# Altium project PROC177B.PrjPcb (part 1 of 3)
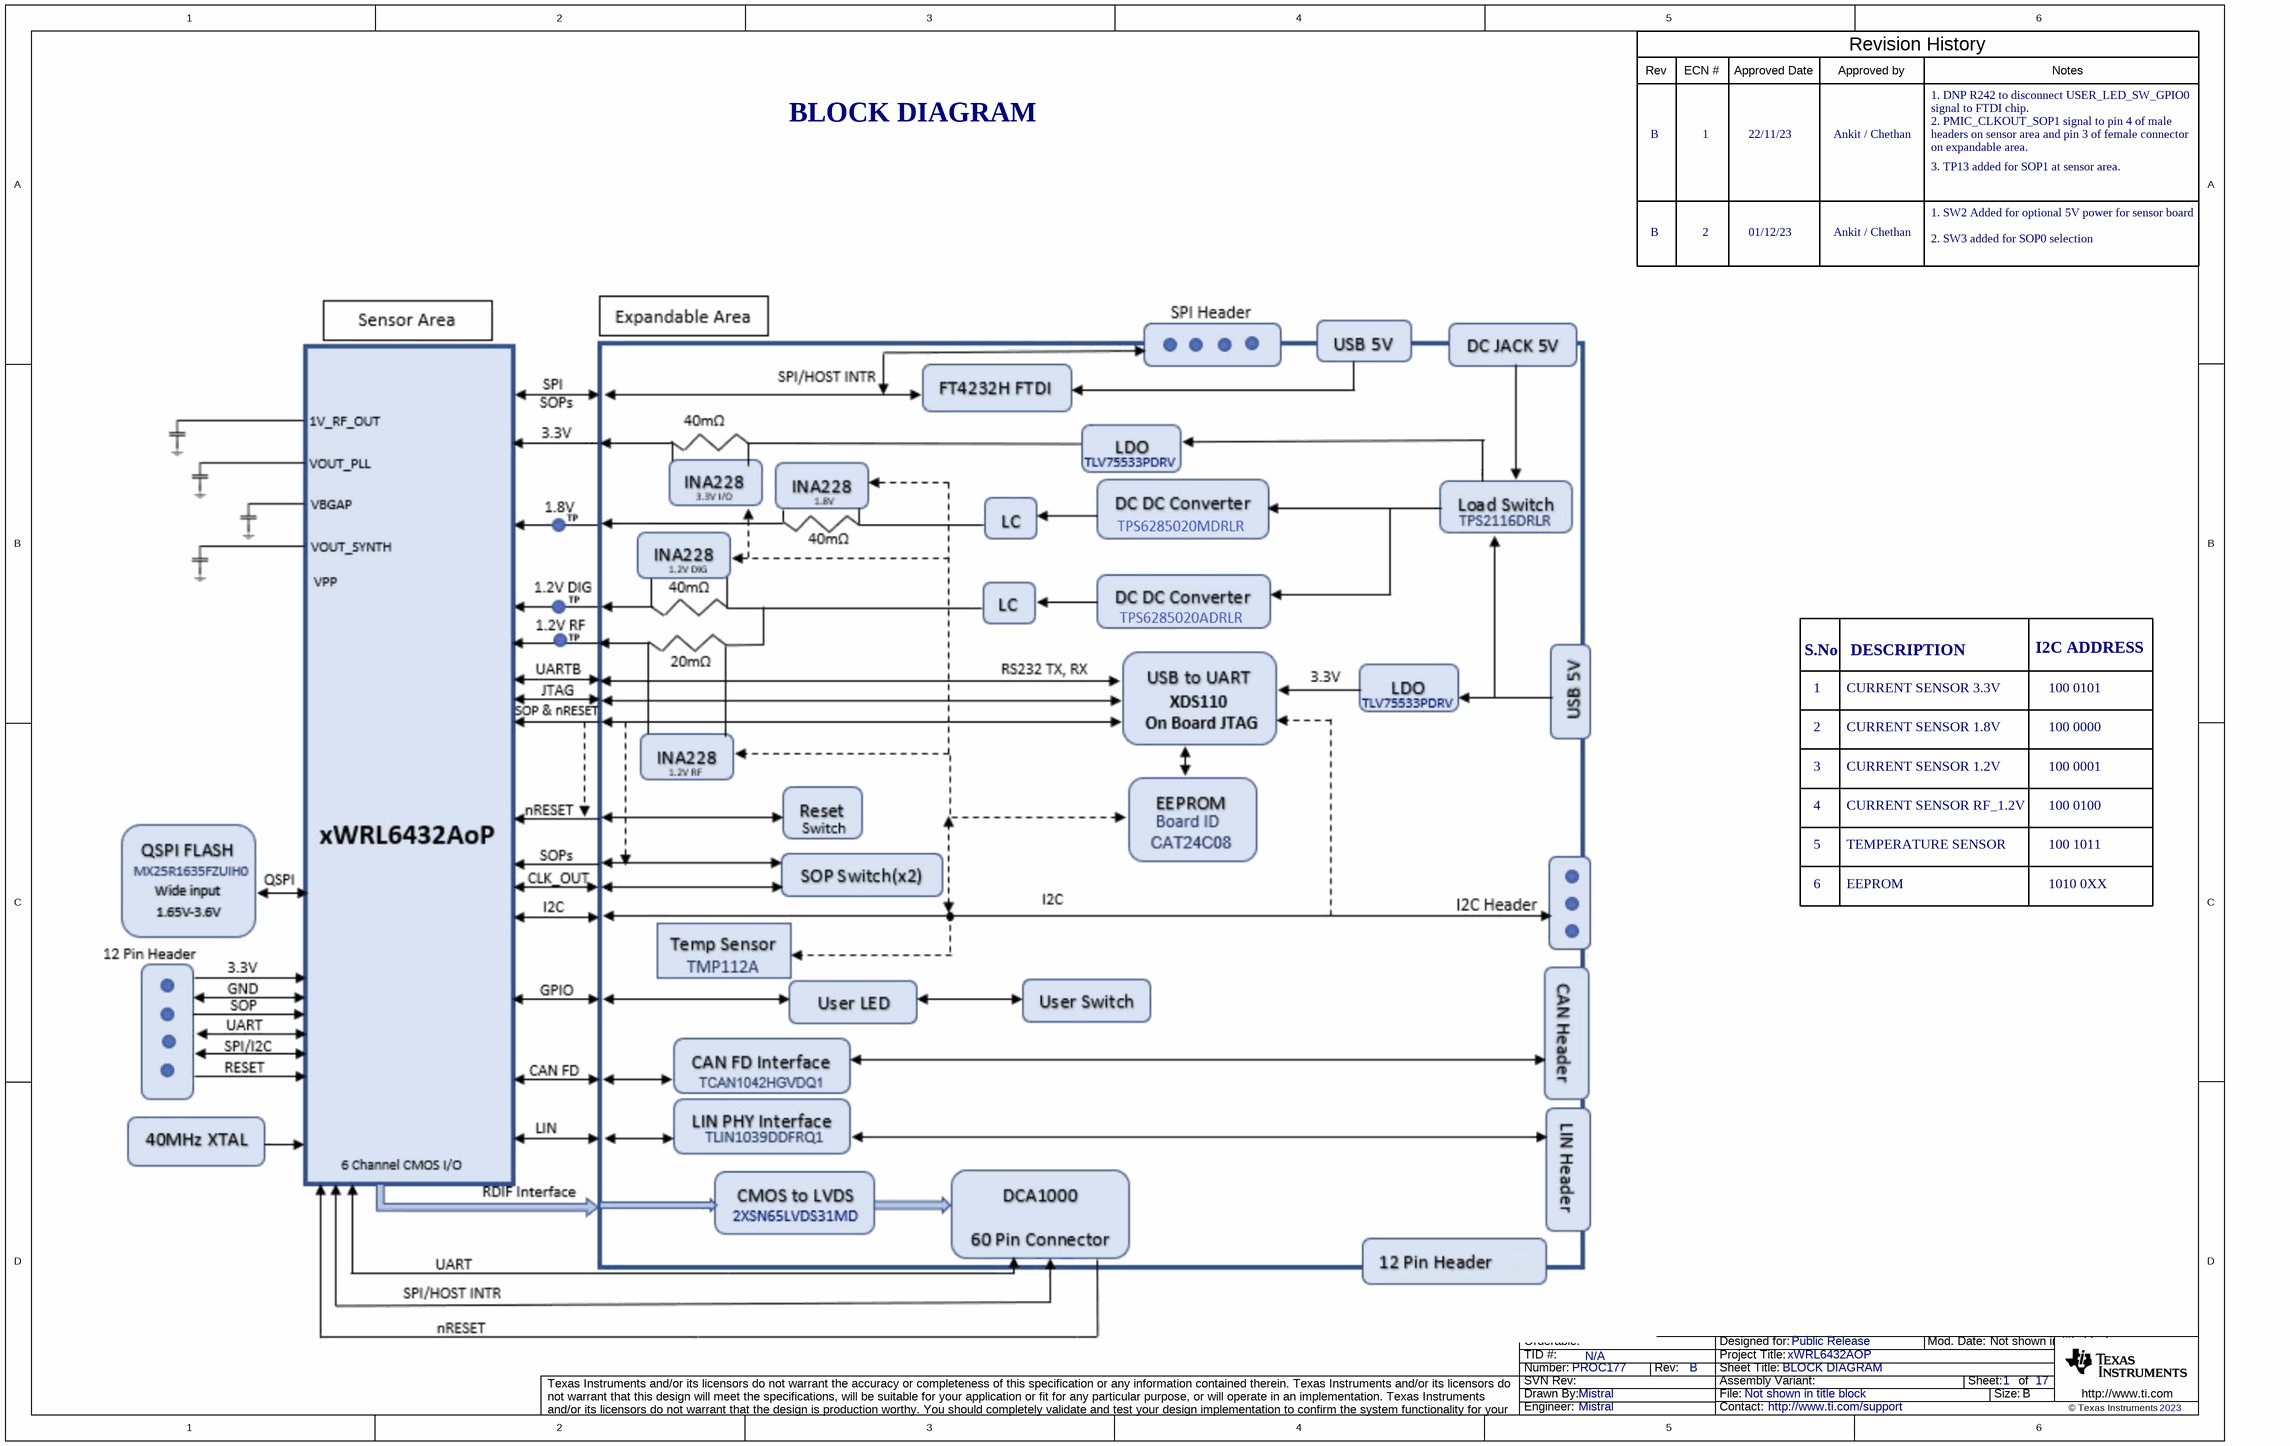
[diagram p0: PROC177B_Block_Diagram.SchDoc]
CopyrightYear: 2023; PCB_Layout: Mistral; PCB_Rev: B; PRJ_Customer: Public Release; PRJ_Engineer: Mistral; PRJ_Number: PROC177; PRJ_Title: xWRL6432AOP; SCH_Rev: B; TechSupport: http://www.ti.com/support; TID: N/A
17 sheets, 464 parts. Net scope: flat (ports and power ports of the same name join across sheets).
Board file: PROC177B_PCB.PcbDoc
Sheets:
  PROC177B_Block_Diagram.SchDoc
  PROC177B_MUX_Block_Diagram.SchDoc
  PROC177B_Table_Of_Contents.SchDoc
  PROC177B_USB_PWR_DC_Jack_Switch.SchDoc
  PROC177B_DC_Regulators.SchDoc
  PROC177B_xWRL6432AoP_Chip.SchDoc
  PROC177B_Decoupling_caps_QSPI_Flash_.SchDoc
  PROC177B_Temp_Current_sensors_EPROM.SchDoc
  PROC177B_LVDS_Driver.SchDoc
  PROC177B_Analog_Mux_SOP_Ctrl.SchDoc
  PROC177B_Analog_MUX_SPI.SchDoc
  PROC177B_XDS110_Interface.SchDoc
  PROC177B_CAN_LIN_PHY_Interface.SchDoc
  PROC177B_FTDI.SchDoc
  PROC177B_DCA1000_Connector_Reset.SchDoc
  PROC177B_I2C_SPI_Connector.SchDoc
  PROC177B_EVM_Hardware.SchDoc

## Sheet PROC177B_Block_Diagram.SchDoc: BLOCK DIAGRAM
size 431 x 279 mm; Date: Not shown in title block; ApprovedBy: Not shown in title block; CheckedBy: Not shown in title block; Author: Not shown in title block; CompanyName: Not shown in title block; DrawnBy: Mistral; Organization: Not shown in title block; Address1: Not shown in title block; Address2: Not shown in title block; Address3: Not shown in title block; Address4: Not shown in title block; DocumentNumber: 1; Revision: Use project parameter SCH_Rev; SheetNumber: 1; SheetTotal: 17; PageSetup: Record=PageOptions¦CenterHorizontal=True¦CenterVertical=True¦PrintScale=1.00¦XCorrection=1.00¦YCorrection=1.00¦PrintKind=0¦BorderSize=5000000¦LeftOffset=0¦BottomOffset=0¦Orientation=2¦PaperLength=1000¦PaperWidth=1000¦Scale=100¦PaperSource=15¦PrintQuality=600¦MediaType=1¦DitherType=10¦PaperKind=Letter¦PrintScaleMode=1

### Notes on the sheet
- Rev
- ECN #
- Approved Date
- Approved by
- Revision History
- Notes
- BLOCK DIAGRAM
- B
- 1
- 22/11/23
- Ankit / Chethan
- 1. DNP R242 to disconnect USER_LED_SW_GPIO0
- signal to FTDI chip.
- 2. PMIC_CLKOUT_SOP1 signal to pin 4 of male
- headers on sensor area and pin 3 of female connector
- on expandable area.
- 3. TP13 added for SOP1 at sensor area.
- 1. SW2 Added for optional 5V power for sensor board
- 2
- 01/12/23
- 2. SW3 added for SOP0 selection
- S.No
- DESCRIPTION
- I2C ADDRESS
- CURRENT SENSOR 3.3V
- CURRENT SENSOR 1.8V
- 100 0000
- 100 0101
- 3
- 4
- CURRENT SENSOR 1.2V
- CURRENT SENSOR RF_1.2V
- 100 0001
- 100 0100
- 5
- TEMPERATURE SENSOR
- 100 1011
- 6
- EEPROM
- 1010 0XX

## Sheet PROC177B_MUX_Block_Diagram.SchDoc: MUX BLOCK DIAGRAM
size 431 x 279 mm; Date: Not shown in title block; ApprovedBy: Not shown in title block; CheckedBy: Not shown in title block; Author: Not shown in title block; CompanyName: Not shown in title block; DrawnBy: Mistral; Engineer: Not shown in title block; Organization: Not shown in title block; Address1: Not shown in title block; Address2: Not shown in title block; Address3: Not shown in title block; Address4: Not shown in title block; DocumentNumber: 2; Revision: Use project parameter SCH_Rev; SheetNumber: 2; SheetTotal: 17; PageSetup: Record=PageOptions¦CenterHorizontal=True¦CenterVertical=True¦PrintScale=1.00¦XCorrection=1.00¦YCorrection=1.00¦PrintKind=0¦BorderSize=5000000¦LeftOffset=0¦BottomOffset=0¦Orientation=2¦PaperLength=1000¦PaperWidth=1000¦Scale=100¦PaperSource=15¦PrintQuality=600¦MediaType=1¦DitherType=10¦PaperKind=Letter¦PrintScaleMode=1
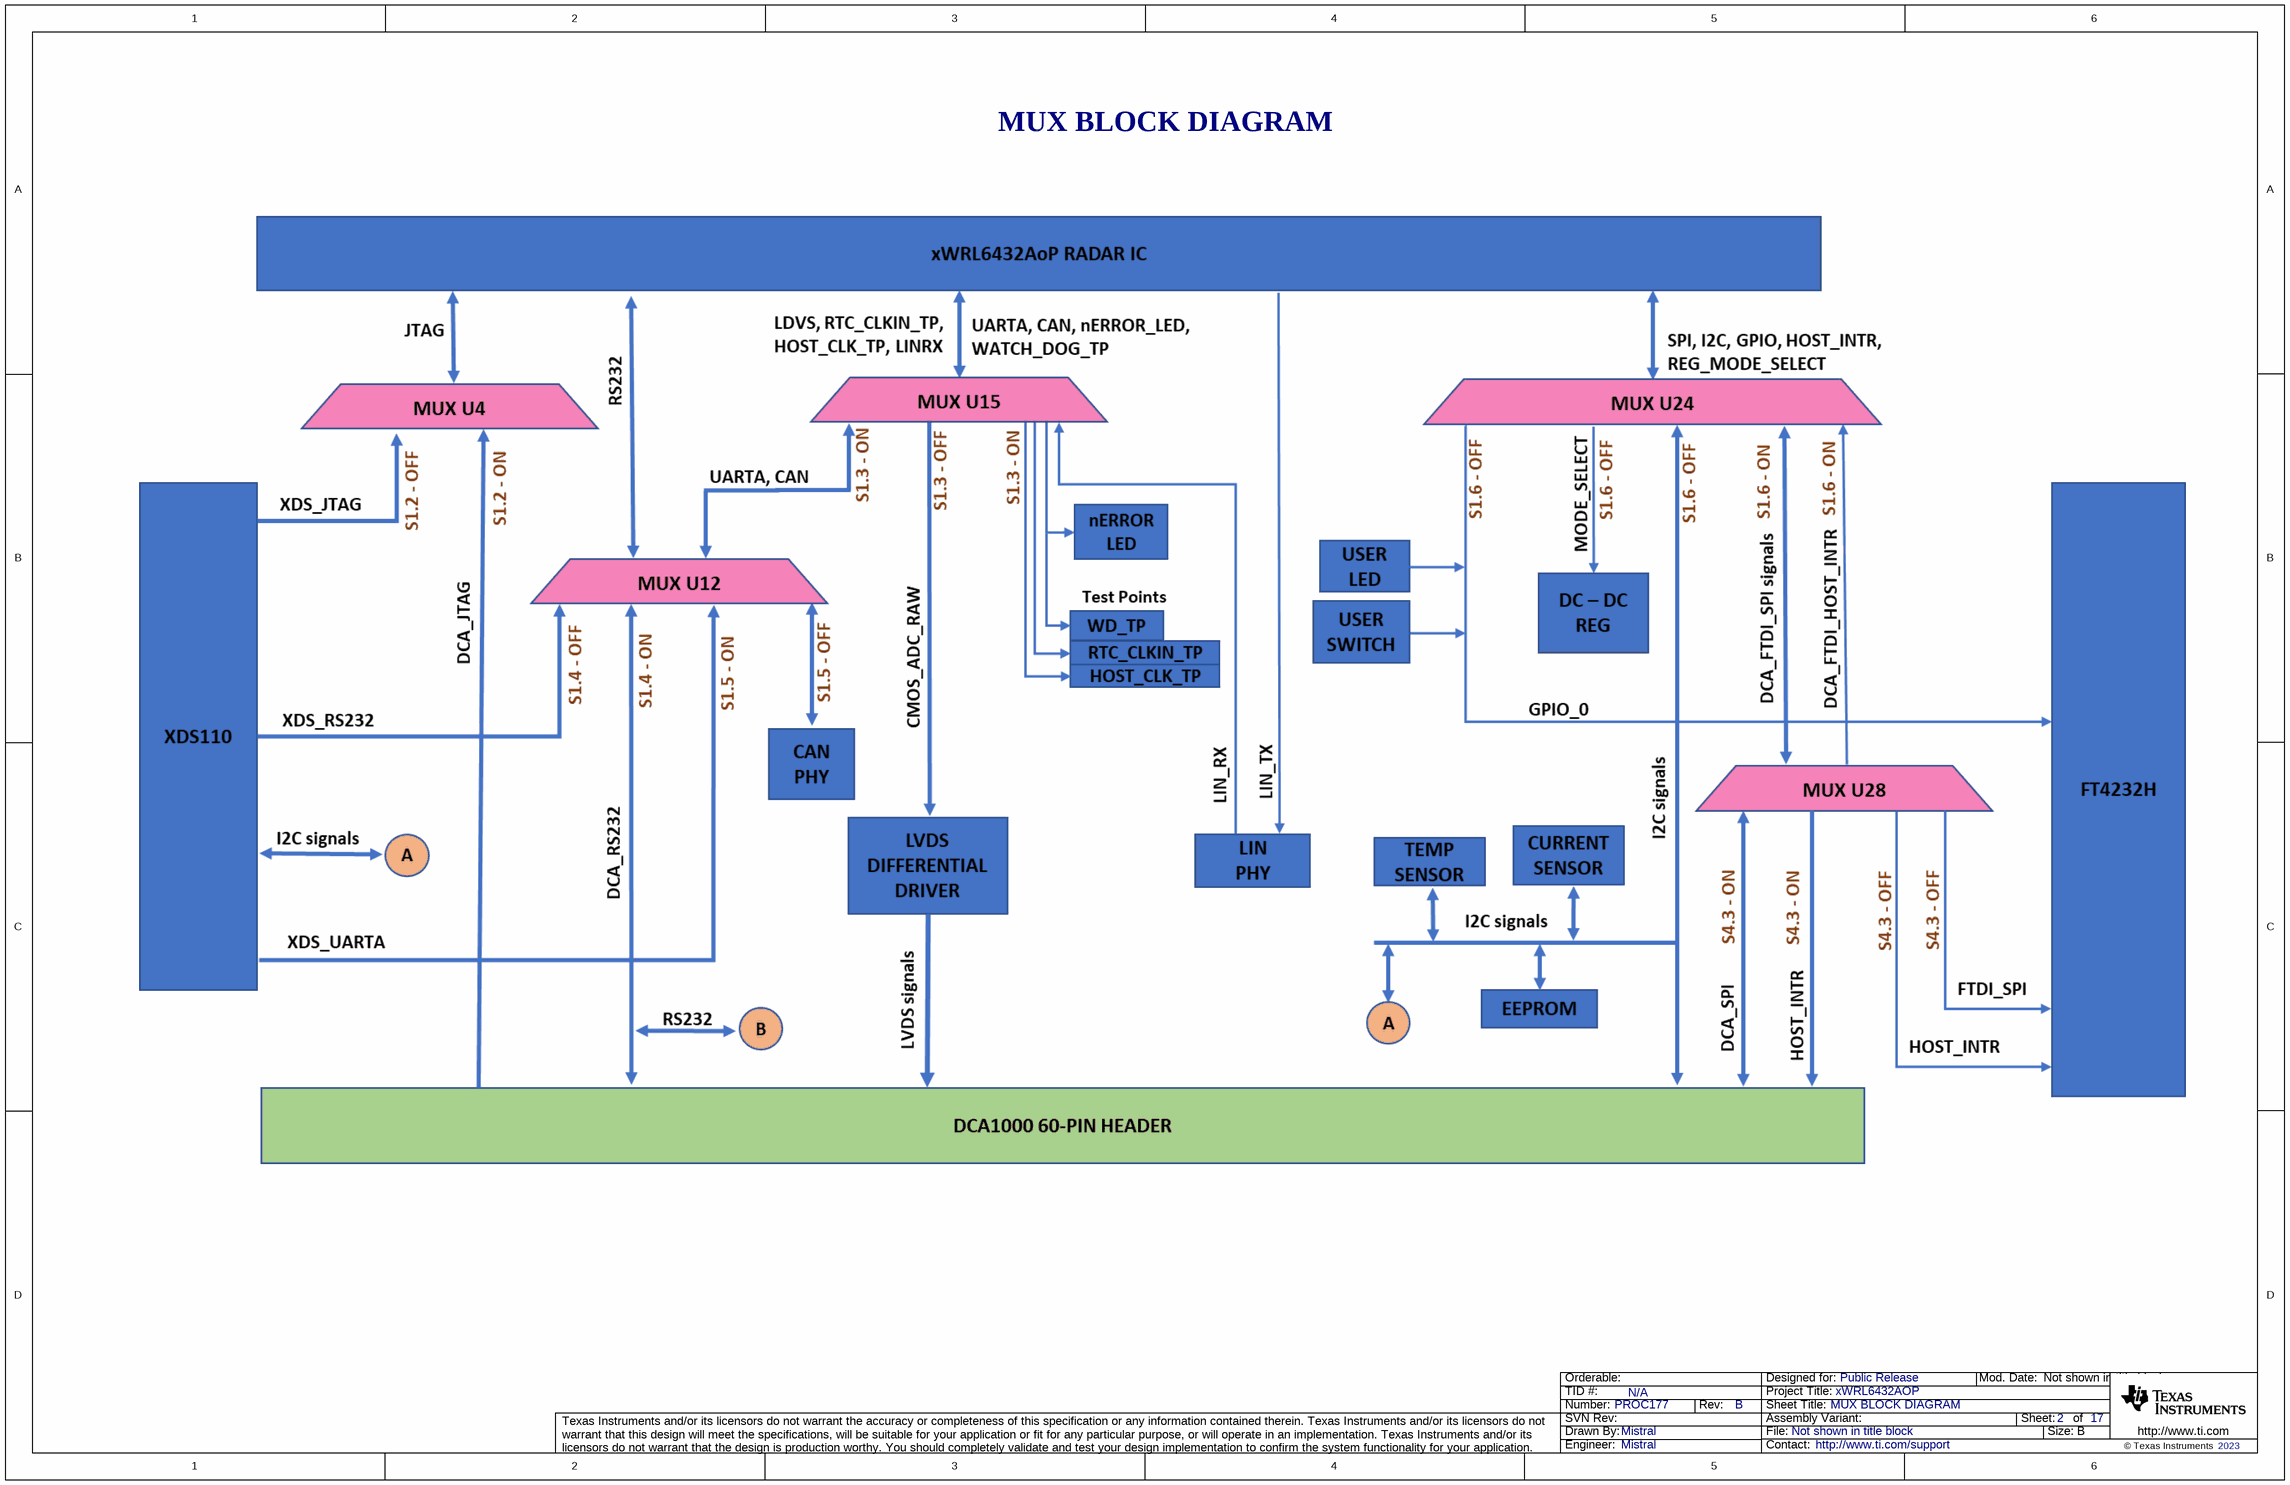
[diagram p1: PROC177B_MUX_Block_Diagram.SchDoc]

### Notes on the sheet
- MUX BLOCK DIAGRAM

## Sheet PROC177B_Table_Of_Contents.SchDoc: TABLE OF CONTENTS
size 431 x 279 mm; Date: Not shown in title block; ApprovedBy: Not shown in title block; CheckedBy: Not shown in title block; Author: Not shown in title block; CompanyName: Not shown in title block; DrawnBy: Mistral; Engineer: Not shown in title block; Organization: Not shown in title block; Address1: Not shown in title block; Address2: Not shown in title block; Address3: Not shown in title block; Address4: Not shown in title block; DocumentNumber: 3; Revision: Use project parameter SCH_Rev; SheetNumber: 3; SheetTotal: 16; PageSetup: Record=PageOptions¦CenterHorizontal=True¦CenterVertical=True¦PrintScale=1.00¦XCorrection=1.00¦YCorrection=1.00¦PrintKind=0¦BorderSize=5000000¦LeftOffset=0¦BottomOffset=0¦Orientation=2¦PaperLength=1000¦PaperWidth=1000¦Scale=100¦PaperSource=15¦PrintQuality=600¦MediaType=1¦DitherType=10¦PaperKind=Letter¦PrintScaleMode=1
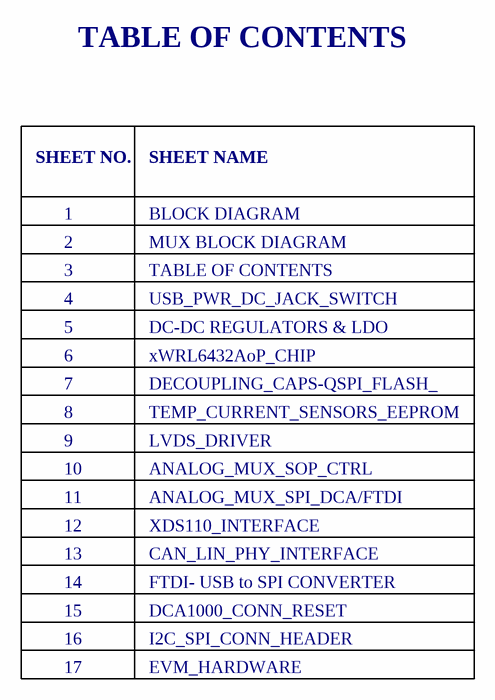
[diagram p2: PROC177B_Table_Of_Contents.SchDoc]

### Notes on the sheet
- TABLE OF CONTENTS
- SHEET NO.
- SHEET NAME
- 1
- 2
- 3
- BLOCK DIAGRAM
- MUX BLOCK DIAGRAM
- 4
- 5
- USB_PWR_DC_JACK_SWITCH
- DC-DC REGULATORS & LDO
- 7
- 8
- 6
- DECOUPLING_CAPS-QSPI_FLASH_
- TEMP_CURRENT_SENSORS_EEPROM
- xWRL6432AoP_CHIP
- 9
- 10
- LVDS_DRIVER
- ANALOG_MUX_SOP_CTRL
- 11
- 12
- 13
- XDS110_INTERFACE
- CAN_LIN_PHY_INTERFACE
- ANALOG_MUX_SPI_DCA/FTDI
- 14
- 15
- DCA1000_CONN_RESET
- FTDI- USB to SPI CONVERTER
- 16
- 17
- I2C_SPI_CONN_HEADER
- EVM_HARDWARE

## Sheet PROC177B_USB_PWR_DC_Jack_Switch.SchDoc: USB_PWR_DC_JACK_SWITCH
size 431 x 279 mm; Date: Not shown in title block; ApprovedBy: Not shown in title block; CheckedBy: Not shown in title block; Author: Not shown in title block; CompanyName: Not shown in title block; DrawnBy: Mistral; Engineer: Not shown in title block; Organization: Not shown in title block; Address1: Not shown in title block; Address2: Not shown in title block; Address3: Not shown in title block; Address4: Not shown in title block; DocumentNumber: 4; Revision: Use project parameter SCH_Rev; SheetNumber: 4; SheetTotal: 17; PageSetup: Record=PageOptions¦CenterHorizontal=True¦CenterVertical=True¦PrintScale=1.00¦XCorrection=1.00¦YCorrection=1.00¦PrintKind=0¦BorderSize=5000000¦LeftOffset=0¦BottomOffset=0¦Orientation=2¦PaperLength=1000¦PaperWidth=1000¦Scale=100¦PaperSource=15¦PrintQuality=600¦MediaType=1¦DitherType=10¦PaperKind=Letter¦PrintScaleMode=1
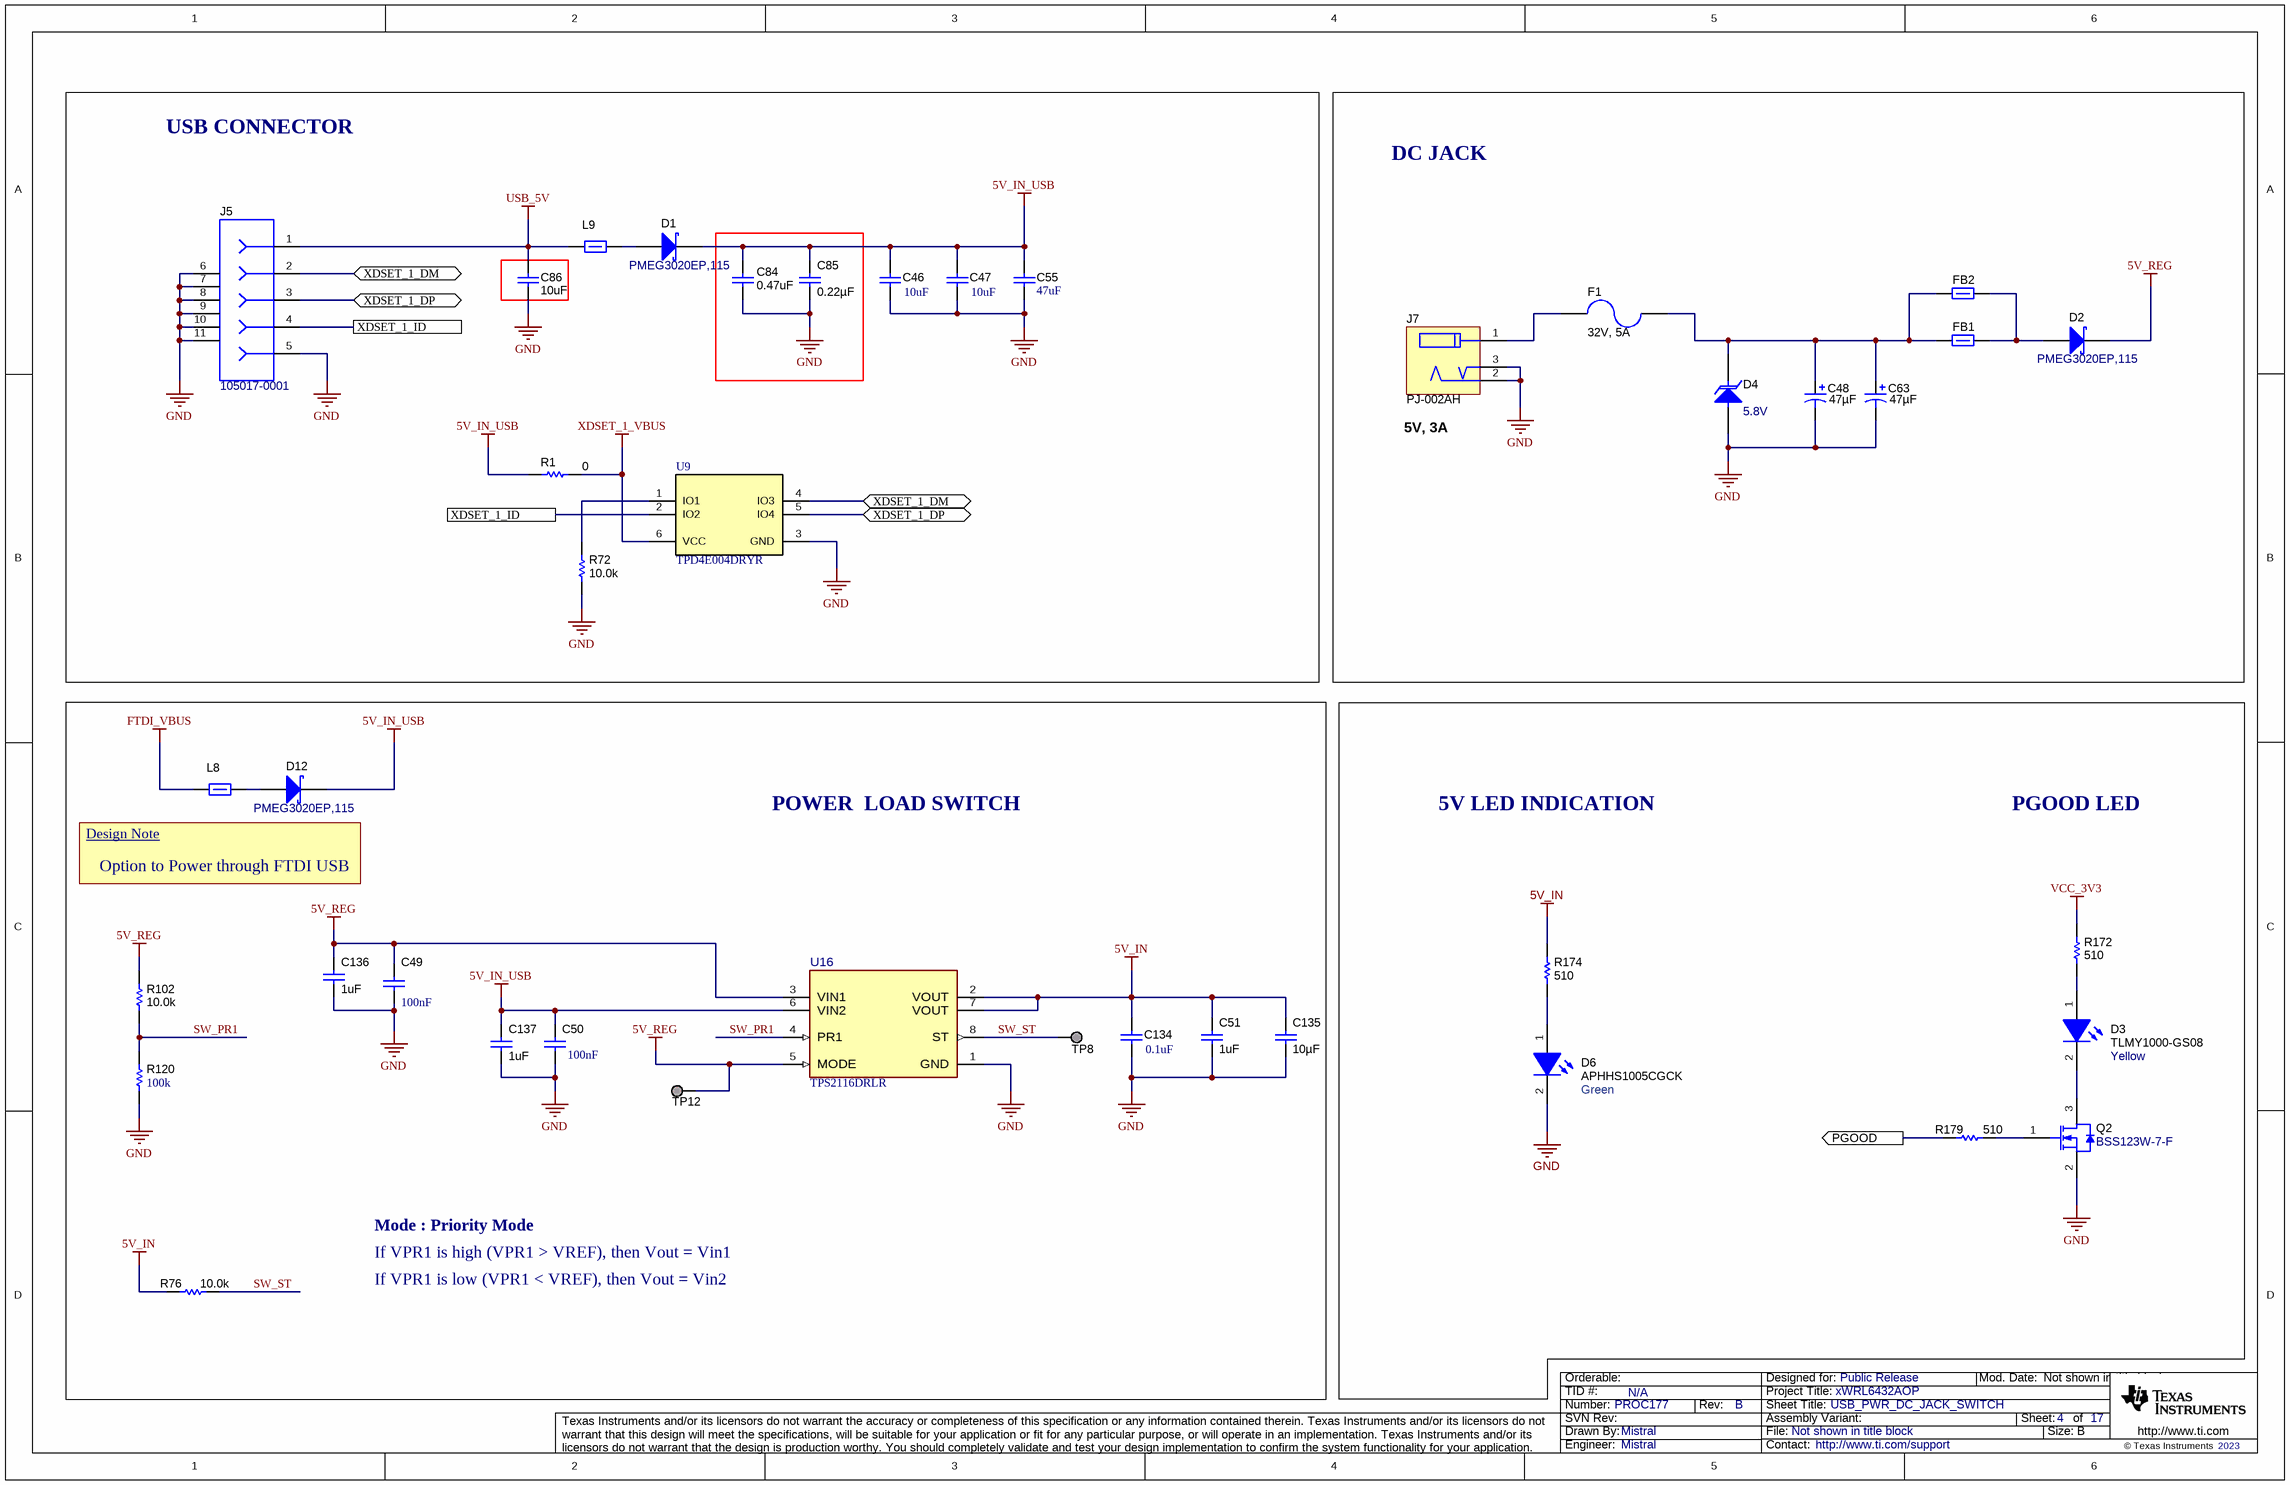
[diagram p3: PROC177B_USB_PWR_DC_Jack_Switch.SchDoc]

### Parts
C46  ValueDisplayed: 10uF  [0402]  (hidden comment: GRM155R61A106ME11D)
C47  ValueDisplayed: 10uF  [0402]  (hidden comment: GRM155R61A106ME11D)
C48  ValueDisplayed: 47µF  [3528-21]  (hidden comment: T491B476K010AT)
C49  Cap_F: 100nF  [0402]  (hidden comment: GCM155R71H104KE02D)
C50  Cap_F: 100nF  [0402]  (hidden comment: GCM155R71H104KE02D)
C51  ValueDisplayed: 1uF  [0402L]  (hidden comment: GRT155C81A105KE01D)
C55  ValueDisplayed: 47uF  [1206_180]  (hidden comment: GRM31CR61A476KE15L)
C63  ValueDisplayed: 47µF  [3528-21]  (hidden comment: T491B476K010AT)
C84  ValueDisplayed: 0.47uF  [0402L]  (hidden comment: GCM155C71A474KE36D)
C85  ValueDisplayed: 0.22µF  [0402L]  (hidden comment: GCM155R71C224KE02D)
C86  ValueDisplayed: 10uF  [0603S]  (hidden comment: GRT188R61A106KE13D)
C134  ValueDisplayed: 0.1uF  [0402]  (hidden comment: GCM155R71H104KE02D)
C135  Cap_F: 10µF  [0603]  (hidden comment: GRM188Z71A106MA73D)
C136  ValueDisplayed: 1uF  [0402L]  (hidden comment: GRT155C81A105KE01D)
C137  ValueDisplayed: 1uF  [0402L]  (hidden comment: GRT155C81A105KE01D)
D1  PMEG3020EP,115  [SOD-128]
D2  PMEG3020EP,115  [SOD-128]
D3  TLMY1000-GS08  value Yellow  [TLMx1000_Yellow]
D4  value 5.8V  [SMB]  (hidden comment: SZP6SMB6.8AT3G)
D6  APHHS1005CGCK  Color: Green  [APHHS1005_Green]
D12  PMEG3020EP,115  [SOD-128]
F1  32V, 5A  [1206]
FB1  BLM21PG300SH1D  [0805_HV]  (value not drawn)
FB2  BLM21PG300SH1D  [0805_HV]  (value not drawn)
J5  105017-0001  [CONN_105017-0001]
J7  PJ-002AH  [CUI_PJ-002AH]
L8  BLM15PD300SZ1D  [0402L]  (value not drawn)
L9  BLM15PD300SZ1D  [0402L]  (value not drawn)
Q2  BSS123W-7-F  [SOT-323]
R1  ValueDisplayed: 0  [0603]  (hidden comment: MCT06030Z0000ZP500)
R72  ValueDisplayed: 10.0k  [0402L]  (hidden comment: CRCW040210K0FKED)
R76  ValueDisplayed: 10.0k  [0402L]  (hidden comment: CRCW040210K0FKED)
R102  ValueDisplayed: 10.0k  [0402L]  (hidden comment: CRCW040210K0FKED)
R120  value 100k  [0402]  (hidden comment: CRCW0402100KFKED)
R172  ValueDisplayed: 510  [0402L]  (hidden comment: ERJ-2GEJ511X)
R174  ValueDisplayed: 510  [0402L]  (hidden comment: ERJ-2GEJ511X)
R179  ValueDisplayed: 510  [0402L]  (hidden comment: ERJ-2GEJ511X)
TP8  TESTPOINT  [TP_25MIL-SMT]  (value not drawn)  (no BOM)
TP12  TESTPOINT  [TP_25MIL-SMT]  (value not drawn)  (no BOM)
U9  TPD4E004DRYR  [DRY0006A]
U16  TPS2116DRLR  [DRL0008A-MFG]

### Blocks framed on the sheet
USB CONNECTOR: C46 C47 C55 C84-C86 D1 J5 L9 R1 R72 U9
DC JACK: C48 C63 D2 D4 F1 FB1 FB2 J7
POWER  LOAD SWITCH: C49-C51 C134-C137 D12 L8 R76 R102 R120 TP8 TP12 U16

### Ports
PGOOD (out), XDSET_1_DM (bidir), XDSET_1_DP (bidir), XDSET_1_ID

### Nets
5V_IN: C51.1 C134.1 C135.1 R76.2 R174.2 U16.2(VOUT) U16.7(VOUT)
5V_IN_USB: C46.2 C47.1 C50.2 C55.1 C84.1 C85.2 C137.1 D1.1(K) D12.1(K) R1.2 U16.6(VIN2)
5V_REG: C49.1 C136.1 D2.1(K) R102.2 TP12.1 U16.3(VIN1) U16.5(MODE)
FTDI_VBUS: L8.1
GND: C46.1 C47.2 C48.2(-) C49.2 C50.1 C51.2 C55.2 C63.2(-) C84.2 C85.1 C86.1 C134.2 C135.2 C136.2 C137.2 D4.2(A) D6.2(K) J5.5 J5.6 J5.7 J5.8 J5.9 J5.10 J5.11 J7.2 J7.3 Q2.2(S) R72.1 R120.1 U9.3(GND) U16.1(GND)
USB_5V: C86.2 J5.1 L9.1
VCC_3V3: R172.2
XDSET_1_VBUS: R1.1 U9.6(VCC)
PGOOD: R179.1 ; port PGOOD
SW_PR1: R102.1 R120.2 U16.4(PR1)
SW_ST: R76.1 TP8.1 U16.8(ST)
XDSET_1_DM: J5.2 U9.4(IO3) ; port XDSET_1_DM
XDSET_1_DP: J5.3 U9.5(IO4) ; port XDSET_1_DP
XDSET_1_ID: J5.4 U9.2(IO2) ; port XDSET_1_ID
NetC48_1: C48.1(+) C63.1(+) D4.1(K) F1.1 FB1.1 FB2.1
NetD1_2: D1.2(A) L9.2
NetD2_2: D2.2(A) FB1.2 FB2.2
NetD3_1: D3.1(A) R172.1
NetD3_2: D3.2(K) Q2.3(D)
NetD6_1: D6.1(A) R174.1
NetD12_2: D12.2(A) L8.2
NetF1_2: F1.2 J7.1
NetQ2_1: Q2.1(G) R179.2
NetR72_2: R72.2 U9.1(IO1)

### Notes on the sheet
- (near J7) 5V, 3A
- Design Note
- 5V LED INDICATION
- PGOOD LED
- Option to Power through FTDI USB
- Mode : Priority Mode
- If VPR1 is high (VPR1 > VREF), then Vout = Vin1
- If VPR1 is low (VPR1 < VREF), then Vout = Vin2

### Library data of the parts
C46 C47 = CMP-0006564-3: CAP, CERM, 10 uF, 10 V, +/- 20%, X5R, 0402; Manufacturer: MuRata; TaMin_C: -55°C; Polarized: N; SizeAreaWB_mm2: 3; Value1: Unknown; U/M: EA; Value: 10uF; TaMax_C: 85°C; SizeZ_mm: 0.6; SizeX_mm: 1; SizeY_mm: 0.5; Value2: 10V; Cap_F: 10µF; AEC Category: Q200
C48 C63 = CMP-0078216-1: CAP, TA, 47 µF, 10 V, +/- 10%, SMD; Manufacturer: Kemet; TaMin_C: -55°C; Polarized: Y; SizeAreaWB_mm2: 17.1; Value: 47uF; TaMax_C: 125°C; SizeZ_mm: 2.1; SizeX_mm: 3.5; SizeY_mm: 2.8; Value2: 10V; SizeArea_mm2: 9.8; CompType: Capacitor; AEC Qualified: N; AEC Category: Q200
C49 C50 = CMP-0006356-2: CAP, CERM, 0.1 uF, 50 V, +/- 10%, X7R, AEC-Q200 Grade 1, 0402; Manufacturer: MuRata; AEC Qualified: Y; SizeZ_mm: 0.6; VDC_V: 50V; AEC Category: Q200; AEC Grade: 1; Polarized: N; SizeArea_mm2: 0.5; SizeAreaWB_mm2: 3; TaMax_C: 125°C; TaMin_C: -55°C; U/M: EA; Value1: Unknown; Value: 0.1uF
C51 C136 C137 = CMP-0006272-2: CAP, CERM, 1 uF, 10 V, +/- 10%, X6S, 0402; Manufacturer: TDK; Polarized: N; Value: 1uF; U/M: EA; Cap_F: 1µF; Value1: Unknown; VDC_V: 16V; TempCo: X5R; TaMin_C: -55°C; TaMax_C: 85°C; Cap_Case: 0402; SizeArea_mm2: 0.5; SizeAreaWB_mm2: 3; SizeX_mm: 1; SizeZ_mm: 0.6; AEC Category: Q200
C55 = CMP-0008944-2: CAP, CERM, 47 uF, 10 V, +/- 10%, X5R, 1206; Manufacturer: MuRata; TaMin_C: -55°C; Polarized: N; SizeAreaWB_mm2: 10.92; Value1: Unknown; U/M: EA; Value: 47uF; TaMax_C: 85°C; SizeZ_mm: 1.8; SizeX_mm: 3.2; SizeY_mm: 1.6; Cap_Case: 1206; Value2: 10V; SizeArea_mm2: 5.12; Cap_F: 47µF; AEC Category: Q200
C84 = CMP-0064967-2: CAP, CERM, 0.47 uF, 10 V,+/- 10%, X7S, 0402; Manufacturer: MuRata; Polarized: N; Value: 0.47uF; U/M: EA; Cap_F: 470nF; Value1: Unknown; VDC_V: 10V; TaMin_C: -55°C; TaMax_C: 125°C; Cap_Case: 0402; SizeArea_mm2: 0.5; SizeAreaWB_mm2: 3; SizeX_mm: 1; SizeZ_mm: 0.6; AEC Category: Q200
C85 = CMP-0078265-1: CAP, CERM, 0.22 µF, 16 V,+/- 10%, X7R, AEC-Q200 Grade 1, 0402; Manufacturer: MuRata; TaMin_C: -55°C; Polarized: N; SizeAreaWB_mm2: 3; U/M: EA; Value: 0.22uF; TaMax_C: 125°C; SizeZ_mm: 0.6; SizeX_mm: 1; SizeY_mm: 0.5; Cap_Case: 0402; Value2: 16V; CompType: Capacitor; AEC Qualified: Y; Cap_F: 220nF; AEC Category: Q200
C86 = CMP-0007497-5: CAP, CERM, 10 uF, 10 V, +/- 10%, X5R, 0603; Manufacturer: MuRata; Polarized: N; Value: 10uF; U/M: EA; Cap_F: 10µF; Tolerance_%: 20%; Value1: Unknown; VDC_V: 10V; TempCo: X7R; TaMin_C: -55°C; TaMax_C: 125°C; Cap_Case: 0603; SizeArea_mm2: 1.28; SizeAreaWB_mm2: 4.68; SizeX_mm: 1.6; SizeY_mm: 0.8; SizeZ_mm: 1; AEC Category: Q200
C134 = CMP-0006356-2: CAP, CERM, 0.1 uF, 50 V, +/- 10%, X7R, AEC-Q200 Grade 1, 0402; Manufacturer: MuRata; TaMin_C: -55°C; Polarized: N; SizeAreaWB_mm2: 3; Value1: Unknown; U/M: EA; Value: 0.1uF; TaMax_C: 125°C; SizeZ_mm: 0.6; SizeX_mm: 1; SizeY_mm: 0.5; Value2: 50V; AEC Qualified: Y; Cap_F: 100nF; AEC Category: Q200
C135 = CMP-0007497-5: CAP, CERM, 10 uF, 10 V, +/- 20%, X7R, 0603; Manufacturer: MuRata; TaMin_C: -55°C; Polarized: N; SizeAreaWB_mm2: 4.68; Value1: Unknown; U/M: EA; Value: 10uF; TaMax_C: 125°C; SizeZ_mm: 1; SizeX_mm: 1.6; SizeY_mm: 0.8; Value2: 10V; SizeArea_mm2: 1.28; AEC Category: Q200
D1 D2 D12 = CMP-0078758-2: Diode, Schottky, 30 V, 2 A, AEC-Q101, SOD-128; Manufacturer: Nexperia; Value2: 0.36V; SizeAreaWB_mm2: 19.6; Io_A: 2A; Value: 30V; AEC Qualified: Y; TJmax_C: 150°C; SizeX_mm: 4.6; AEC Category: Q101; SizeY_mm: 2.5; SizeArea_mm2: 11.5; Vf_V: 3.6dV; SizeZ_mm: 1.1
D3 = CMP-0078196-2: LED, Yellow, SMD; Manufacturer: Vishay-Semiconductor; Tjmax_C: 120°C; SizeAreaWB_mm2: 4.68; Vr_V: 6V; Power_TotalModule: 40mW; Angle: 160; SizeArea_mm2: 1.28; Ir_A: 10µA; SizeZ_mm: 0.65; Io_A: 2mA; Vf_V: 1.8V; SizeY_mm: 0.8; Value1: .04W; SizeX_mm: 1.6; Type: AlInGaP
D4 = CMP-0078243-3: Diode, TVS, Uni, 5.8 V, 10.5 Vc, AEC-Q101, SMB; Manufacturer: Littelfuse; SizeAreaWB_mm2: 44.156; Value1: 0.55W; RJA_CperW: 226; SizeZ_mm: 2.6; SizeX_mm: 5.6; SizeY_mm: 3.81; SizeArea_mm2: 21.336; AEC Qualified: Y; AEC Category: Q101; Vc: 10.5V
D6 = CMP-0067682-2: LED, Green, SMD; Manufacturer: Kingbright; Angle: 120.0; Power_TotalModule: 75mW; SizeZ_mm: 0.6; Vf_V: 2.1V; Vr_V: 5V; Io_A: 20mA; Ir_A: 10µA; SizeArea_mm2: 0.5; SizeAreaWB_mm2: 3.0; SizeX_mm: 1.0; Tjmax_C: 85°C; Value1: 0.075W
F1 = CMP-0003458-2: Fuse, 5 A, 32VAC/VDC, SMD; Manufacturer: Littelfuse; PartNumber: 0440005.WR; SizeAreaWB_mm2: 10.92; Interrupt_AC: 50A; SizeZ_mm: 1.35; SizeX_mm: 3.2; SizeY_mm: 1.6; SizeArea_mm2: 5.12; Rtyp_Ohm: 0.012; MeltingTyp: 4.761
FB1 = CMP-0003364-1: Ferrite Bead, 30 ohm @ 100 MHz, 4 A, 0805; Manufacturer: MuRata; ZTyp@100MHz_Ohm: 30; SizeAreaWB_mm2: 6.75; DCR_ohm: 0.014; Value1: 0.014 ohm; Value: 30 ohm; Imax_A: 4A; SizeZ_mm: 1.45; SizeX_mm: 2; SizeY_mm: 1.25; SizeArea_mm2: 2.5; INSTALLATION: DNP
FB2 = CMP-0003364-1: Ferrite Bead, 30 ohm @ 100 MHz, 4 A, 0805; Manufacturer: MuRata; ZTyp@100MHz_Ohm: 30; SizeAreaWB_mm2: 6.75; DCR_ohm: 0.014; Value1: 0.014 ohm; Value: 30 ohm; Imax_A: 4A; SizeZ_mm: 1.45; SizeX_mm: 2; SizeY_mm: 1.25; SizeArea_mm2: 2.5
J5 = CMP-0055293-1: Connector, Receptacle, Micro-USB Type B, R/A, Bottom Mount SMT; Manufacturer: Molex; CNHeader: FALSE; CompType: USB; CT: TRUE; Gender: Female; Green_Lifecycle: Active; Green_REACh: Passed
J7 = CMP-0078270-1: DC POWER JACK, R/A, TH; Manufacturer: CUI Inc.; Gender: Female; Cert_UL: Y; Current_A: 5A; Voltage_V: 4.5-5.5V; Green_REACh: Incomplete; Green_Lifecycle: Not Set
L8 L9 = CMP-0078934-1: Inductor, Ferrite Bead, Ferrite, 2.2 A, 0.035 ohm, AEC-Q200 Grade 1, SMD; Manufacturer: MuRata; AEC Category: Q200; AEC Grade: 1; AEC Qualified: Y; DCR_ohm: 0.035; Imax_A: 2.2A; SizeArea_mm2: 0.5; SizeAreaWB_mm2: 3; SizeZ_mm: 0.6
Q2 = CMP-0000948-2: MOSFET, N-CH, 100 V, 0.17 A, SOT-323; Alternate Manufacturer: None; Manufacturer: Diodes Inc.; SizeZ_mm: 1.1; ChType: N; Value1: 1; VdsMax_V: 100V; SizeX_mm: 2.2; Vgs_V: 20V; Value: 100V; Rdson45_ohm: 10; SizeArea_mm2: 4.84; AEC Category: Q101; IdsMax_A: 1.7dA; SizeAreaWB_mm2: 10.24; U/M: EA
R1 = CMP-0025884-3: RES, 0, 5%, 0.125 W, 0603; Manufacturer: Vishay/Beyschlag; Power_W: 125mW; TempCo: ppm/C; Value_Code: 0000; U/M: EA; Value: 0; EIA_Code: E24; SizeX_mm: 1.6; SizeY_mm: 0.8; SizeZ_mm: 1; Value2: 0.125W; SizeArea_mm2: 1.28; AEC Qualified: N; AEC Category: Q200
R72 R76 R102 = CMP-0025958-3: RES, 10.0 k, 1%, 0.063 W, AEC-Q200 Grade 0, 0402; Manufacturer: Vishay-Dale; Power_W: 63mW; TempCo: 100 ppm/C; Value_Code: 10k0; Value: 10.0k; EIA_Code: E96; Res_ohm: 10k; SizeX_mm: 1; SizeY_mm: 0.5; SizeZ_mm: 0.6; Value2: 0.063W; AEC Qualified: Y; VDC_V: 50V; AEC Category: Q200; AEC Grade: 0
R120 = CMP-0025950-3: RES, 100 k, 1%, 0.063 W, AEC-Q200 Grade 0, 0402; Manufacturer: Vishay-Dale; AEC Category: Q200; AEC Grade: 0; AEC Qualified: Y; EIA_Code: E96; Power_W: 63mW; SizeArea_mm2: 0.5; SizeX_mm: 1; SizeZ_mm: 0.6; TempCo: 100 ppm/C; Value2: 0.063W; VDC_V: 50V
R172 R174 R179 = CMP-0078212-1: RES, 510, 5%, 0.1 W, AEC-Q200 Grade 0, 0402; Manufacturer: Panasonic; Value_Code: 510R; SizeArea_mm2: 0.5; AEC Qualified: Y; AEC Category: Q200; Value: 510; SizeZ_mm: 0.6; EIA_Code: E24; TempCo: 200 ppm/C; AEC Grade: 0; Power_W: 100mW; VDC_V: 50V; Value2: 0.1W; U/M: EA; SizeX_mm: 1
TP8 TP12 = CMP-0078143-3: TEST POINT.  No entry in BOM.
U9 = CMP-0043115-3: 4-Channel ESD Protection Array for High-Speed Data Interfaces, DRY0006A (USON-6); Manufacturer: Texas Instruments; IO Leakage Current(nA): 1; USB High Speed: TRUE; IO Capacitance(Typ)(pF): 1.6; Eco-Plan: Green (RoHS & no Sb/Br); IEC 61000-4-2 Contact(+/- kV): 8; Breakdown Voltage(Min)(V): 6; IEC 61000-4-2 Air-Gap(+/- kV): 12; AEC Category: Q200; AEC Qualified: N; CompType: IC; SizeAreaWB_mm2: 4.9; SizeArea_mm2: 1.45; SizeX_mm: 1.0; SizeZ_mm: 0.6; Rating: Catalog
U16 = CMP-0088593-2: 1.6 V to 5 V, 2.5-A Low IQ Power Mux With Manual and Automatic Switchover; Manufacturer: Texas Instruments; Max Supply Voltage: 5.5V; TaMax_C: +125°C; Output Voltage: 0-5.5V; CompType: IC; Min Supply Voltage: 1.6V; TaMin_C: -55°C; SizeZ_mm: 0.6mm; AEC Category: Q200; Nominal Supply Current: 0.5-1uA; Number Of Outputs: 1; Standoff Height: 0mm; AEC Qualified: No

## Sheet PROC177B_DC_Regulators.SchDoc: DC_REGULATORS & LDO
size 431 x 279 mm; Date: Not shown in title block; ApprovedBy: Not shown in title block; CheckedBy: Not shown in title block; Author: Not shown in title block; CompanyName: Not shown in title block; DrawnBy: Mistral; Engineer: Not shown in title block; Organization: Not shown in title block; Address1: Not shown in title block; Address2: Not shown in title block; Address3: Not shown in title block; Address4: Not shown in title block; DocumentNumber: 5; Revision: Use project parameter SCH_Rev; SheetNumber: 5; SheetTotal: 17; PageSetup: Record=PageOptions¦CenterHorizontal=True¦CenterVertical=True¦PrintScale=1.00¦XCorrection=1.00¦YCorrection=1.00¦PrintKind=0¦BorderSize=5000000¦LeftOffset=0¦BottomOffset=0¦Orientation=2¦PaperLength=1000¦PaperWidth=1000¦Scale=100¦PaperSource=15¦PrintQuality=600¦MediaType=1¦DitherType=10¦PaperKind=Letter¦PrintScaleMode=1
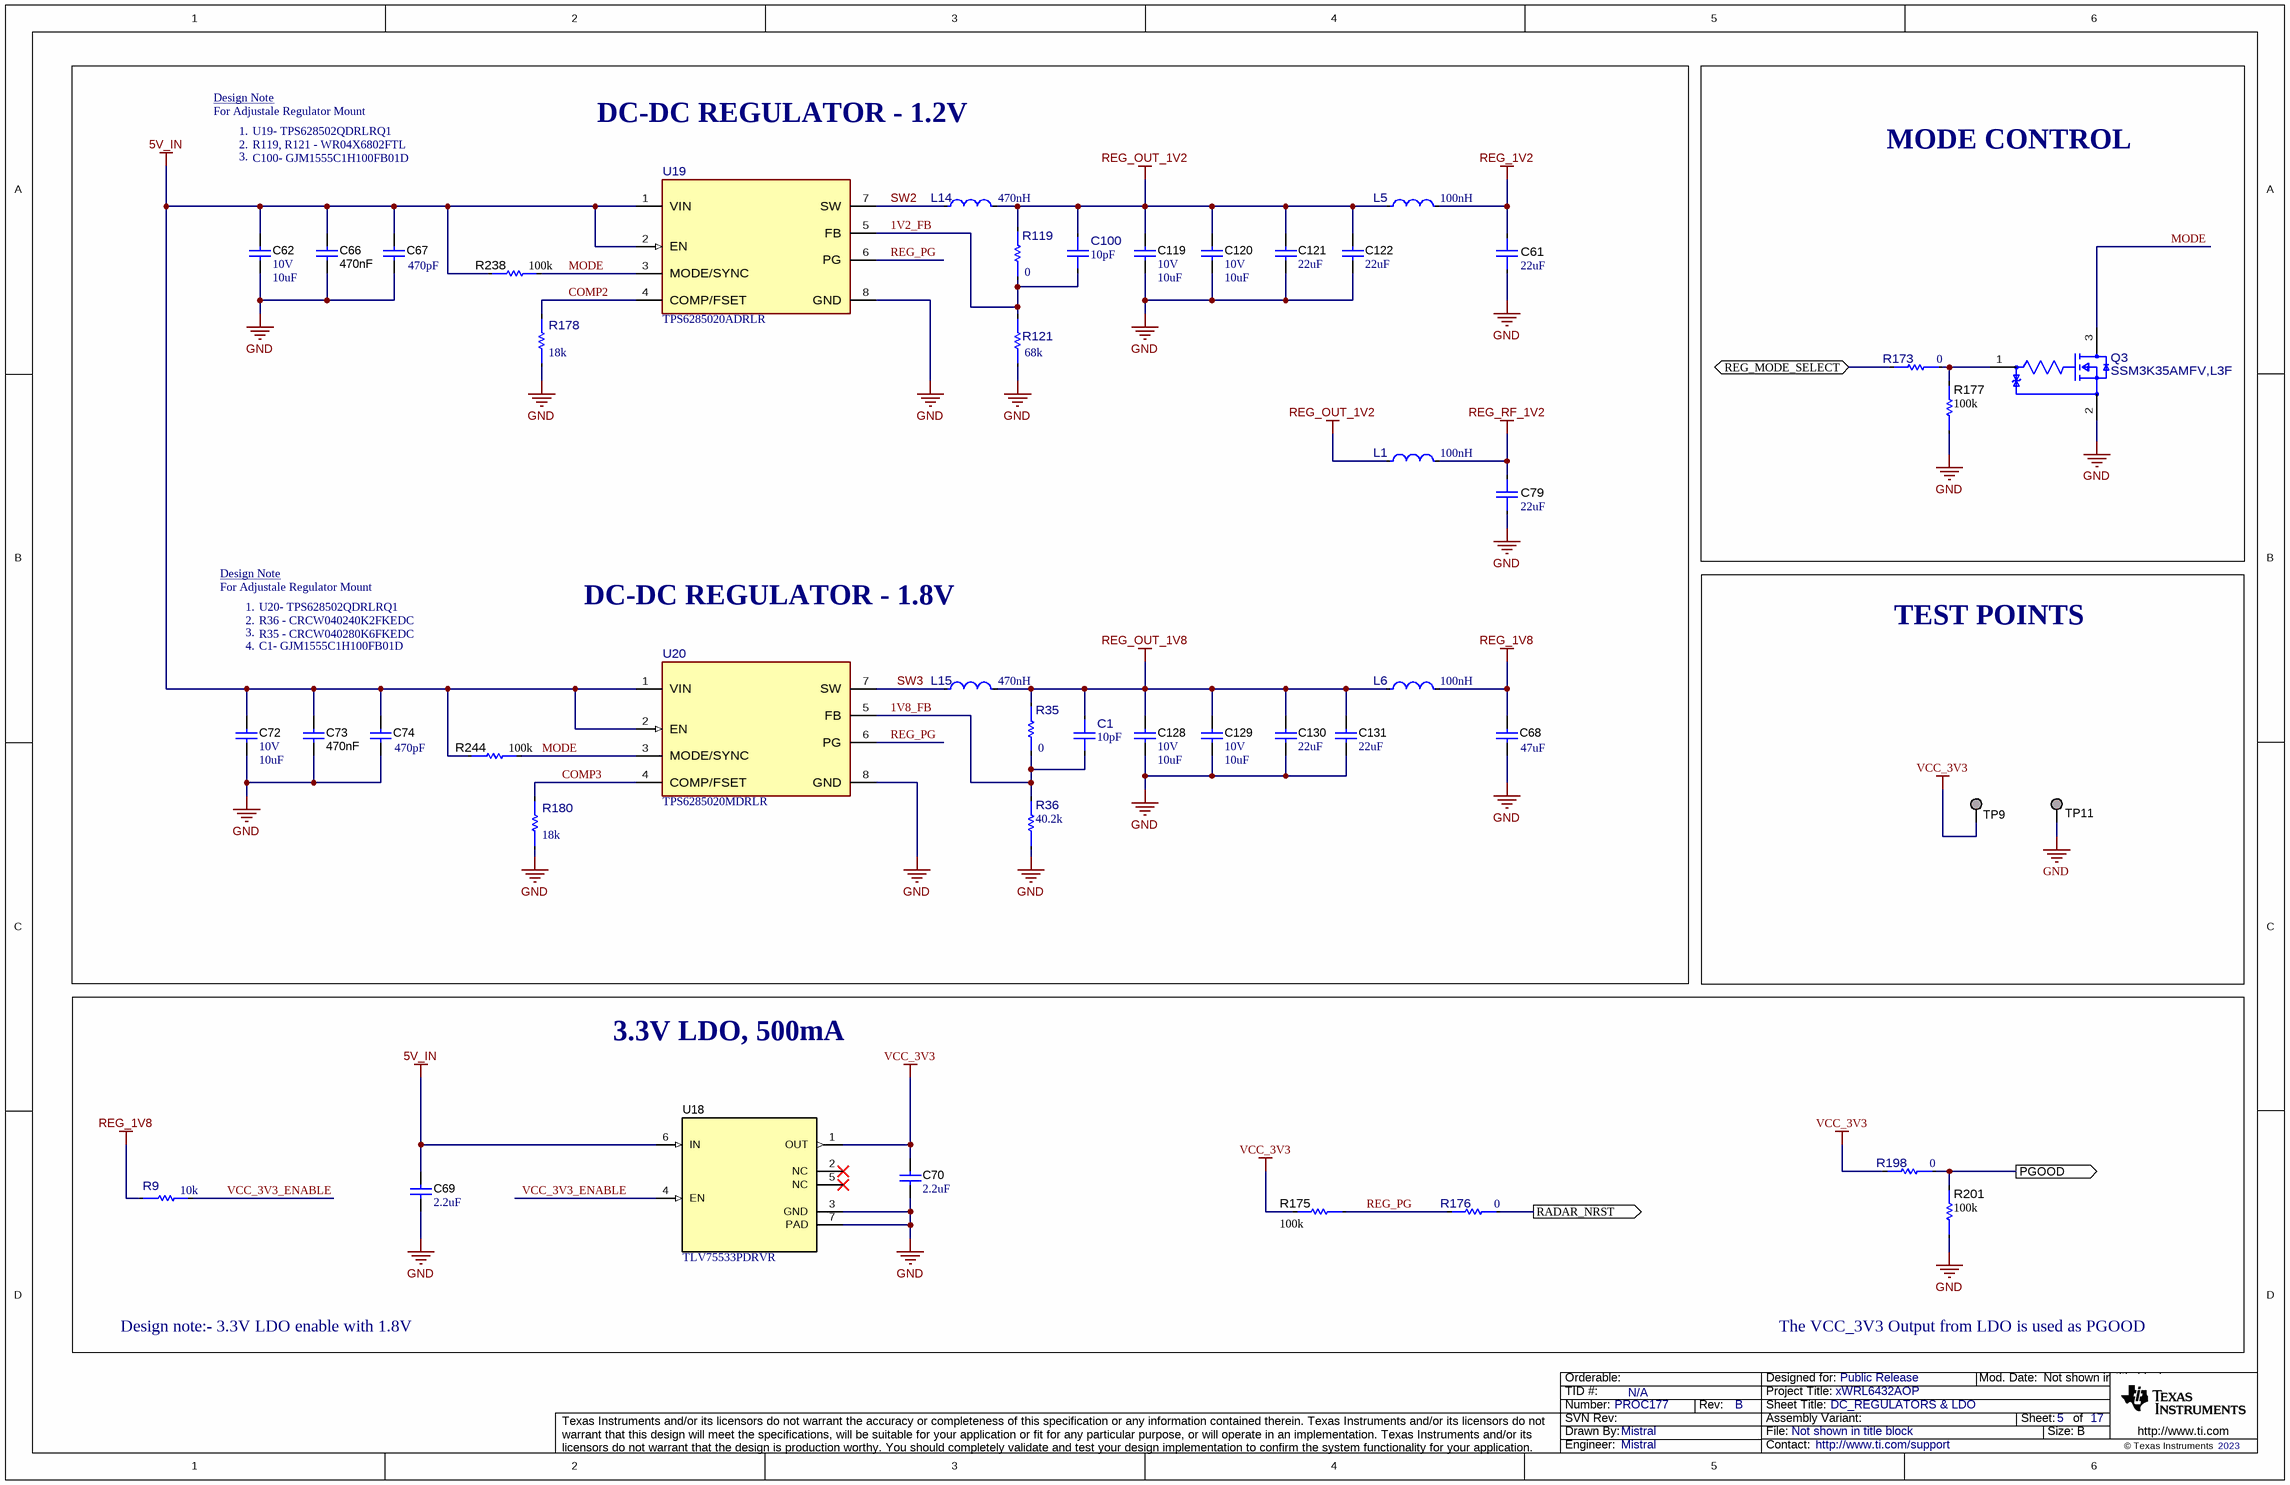
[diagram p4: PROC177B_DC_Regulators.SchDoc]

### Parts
C1  ValueDisplayed: 10pF  [FP-GJM1555C1H100FB01D_0402-MFG]  (hidden comment: GJM1555C1H100FB01D)
C61  ValueDisplayed: 22uF  [FP-GRM31CR70J226ME19K_1206-MFG]  (hidden comment: GRM31CR70J226ME19K)
C62  VDC_V: 10V  ValueDisplayed: 10uF  [0603]  (hidden comment: GRM188C81A106MA73D)
C66  Cap_F: 470nF  [0603S]  (hidden comment: GRM188R71C474KA88D)
C67  ValueDisplayed: 470pF  [0402L]  (hidden comment: GRM1555C1H471JA01D)
C68  ValueDisplayed: 47uF  [1206_180]  (hidden comment: GRM31CR60J476ME19L)
C69  ValueDisplayed: 2.2uF  [0402S]  (hidden comment: GRM155C81C225KE11D)
C70  ValueDisplayed: 2.2uF  [0402S]  (hidden comment: GRM155C81C225KE11D)
C72  VDC_V: 10V  ValueDisplayed: 10uF  [0603]  (hidden comment: GRM188C81A106MA73D)
C73  Cap_F: 470nF  [0603S]  (hidden comment: GRM188R71C474KA88D)
C74  ValueDisplayed: 470pF  [0402L]  (hidden comment: GRM1555C1H471JA01D)
C79  ValueDisplayed: 22uF  [FP-GRM31CR70J226ME19K_1206-MFG]  (hidden comment: GRM31CR70J226ME19K)
C100  ValueDisplayed: 10pF  [FP-GJM1555C1H100FB01D_0402-MFG]  (hidden comment: GJM1555C1H100FB01D)
C119  VDC_V: 10V  ValueDisplayed: 10uF  [0603]  (hidden comment: GRM188C81A106MA73D)
C120  VDC_V: 10V  ValueDisplayed: 10uF  [0603]  (hidden comment: GRM188C81A106MA73D)
C121  ValueDisplayed: 22uF  [1206_180L]  (hidden comment: C3216X6S1A226M160AB)
C122  ValueDisplayed: 22uF  [1206_180L]  (hidden comment: C3216X6S1A226M160AB)
C128  VDC_V: 10V  ValueDisplayed: 10uF  [0603]  (hidden comment: GRM188C81A106MA73D)
C129  VDC_V: 10V  ValueDisplayed: 10uF  [0603]  (hidden comment: GRM188C81A106MA73D)
C130  ValueDisplayed: 22uF  [1206_180L]  (hidden comment: C3216X6S1A226M160AB)
C131  ValueDisplayed: 22uF  [1206_180L]  (hidden comment: C3216X6S1A226M160AB)
L1  Ind_H: 100nH  [FP-LQM2MPZR10MJHL_0806 (2016)-MFG]  (hidden comment: LQM2MPZR10MJHL)
L5  Ind_H: 100nH  [FP-LQM2MPZR10MJHL_0806 (2016)-MFG]  (hidden comment: LQM2MPZR10MJHL)
L6  Ind_H: 100nH  [FP-LQM2MPZR10MJHL_0806 (2016)-MFG]  (hidden comment: LQM2MPZR10MJHL)
L14  Ind_H: 470nH  [FP-DFE201210U-R47M=P2_0805 (2012)-MFG]  (hidden comment: DFE201210U-R47M=P2)
L15  Ind_H: 470nH  [FP-DFE201210U-R47M=P2_0805 (2012)-MFG]  (hidden comment: DFE201210U-R47M=P2)
Q3  SSM3K35AMFV,L3F  [FP-SSM3K35AMFV,L3F_SOT-723-MFG]
R9  value 10k  [FP-RC0402FR-0710KL_0402-IPC_B]  (hidden comment: RC0402FR-0710KL)
R35  value 0  [FP-RC0402JR-070RP_0402-MFG]  (hidden comment: RC0402JR-070RP)
R36  value 40.2k  [FP-CRCW040240K2FKEDC_0402-MFG]  (hidden comment: CRCW040240K2FKEDC)
R119  value 0  [FP-RC0402JR-070RP_0402-MFG]  (hidden comment: RC0402JR-070RP)
R121  value 68k  [FP-WR04X6802FTL_0402-MFG]  (hidden comment: WR04X6802FTL)
R173  value 0  [FP-RC0402JR-070RP_0402-MFG]  (hidden comment: RC0402JR-070RP)
R175  Res_ohm: 100k  [FP-CRCW0402100KFKEDC_0402-IPC_B]  (hidden comment: CRCW0402100KFKEDC)
R176  value 0  [FP-RC0402JR-070RP_0402-MFG]  (hidden comment: RC0402JR-070RP)
R177  Res_ohm: 100k  [FP-CRCW0402100KFKEDC_0402-IPC_B]  (hidden comment: CRCW0402100KFKEDC)
R178  value 18k  [FP-CRCW040218K0FKEDC_0402-IPC_B]  (hidden comment: CRCW040218K0FKEDC)
R180  value 18k  [FP-CRCW040218K0FKEDC_0402-IPC_B]  (hidden comment: CRCW040218K0FKEDC)
R198  value 0  [FP-RC0402JR-070RP_0402-MFG]  (hidden comment: RC0402JR-070RP)
R201  Res_ohm: 100k  [FP-CRCW0402100KFKEDC_0402-IPC_B]  (hidden comment: CRCW0402100KFKEDC)
R238  Res_ohm: 100k  [FP-CRCW0402100KFKEDC_0402-IPC_B]  (hidden comment: CRCW0402100KFKEDC)
R244  Res_ohm: 100k  [FP-CRCW0402100KFKEDC_0402-IPC_B]  (hidden comment: CRCW0402100KFKEDC)
TP9  TESTPOINT  [TP_25MIL-SMT]  (value not drawn)  (no BOM)
TP11  TESTPOINT  [TP_VIA_060RND040]  (value not drawn)  (no BOM)
U18  TLV75533PDRVR  [DRV0006A]
U19  TPS6285020ADRLR  [DRL0008A-MFG]
U20  TPS6285020MDRLR  [DRL0008A-MFG]

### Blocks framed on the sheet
MODE CONTROL: Q3 R173 R177
TEST POINTS: TP9 TP11
3.3V LDO, 500mA: C69 C70 R9 R175 R176 R198 R201 U18

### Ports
PGOOD (out), RADAR_NRST (out), REG_MODE_SELECT (bidir)

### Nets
5V_IN: C62.1 C66.1 C67.1 C69.2 C72.1 C73.1 C74.1 R238.1 R244.1 U18.6(IN) U19.1(VIN) U19.2(EN) U20.1(VIN) U20.2(EN)
GND: C61.1 C62.2 C66.2 C67.2 C68.1 C69.1 C70.1 C72.2 C73.2 C74.2 C79.1 C119.2 C120.2 C121.1 C122.1 C128.2 C129.2 C130.1 C131.1 Q3.2(S) R36.1 R121.1 R177.1 R178.1 R180.1 R201.1 TP11.1 U18.3(GND) U18.7(PAD) U19.8(GND) U20.8(GND)
REG_1V2: C61.2 L5.2
REG_1V8: C68.2 L6.2 R9.1
REG_OUT_1V2: C100.1 C119.1 C120.1 C121.2 C122.2 L1.1 L5.1 L14.2 R119.2
REG_OUT_1V8: C1.1 C128.1 C129.1 C130.2 C131.2 L6.1 L15.2 R35.1
REG_RF_1V2: C79.2 L1.2
VCC_3V3: C70.2 R175.2 R198.2 TP9.1 U18.1(OUT)
1V2_FB: C100.2 R119.1 R121.2 U19.5(FB)
1V8_FB: C1.2 R35.2 R36.2 U20.5(FB)
COMP2: R178.2 U19.4(COMP/FSET)
COMP3: R180.2 U20.4(COMP/FSET)
MODE: Q3.3(D) R238.2 R244.2 U19.3(MODE/SYNC) U20.3(MODE/SYNC)
PGOOD: R198.1 R201.2 ; port PGOOD
RADAR_NRST: R176.1 ; port RADAR_NRST
REG_MODE_SELECT: R173.2 ; port REG_MODE_SELECT
REG_PG: R175.1 R176.2 U19.6(PG) U20.6(PG)
SW2: L14.1 U19.7(SW)
SW3: L15.1 U20.7(SW)
VCC_3V3_ENABLE: R9.2 U18.4(EN)
NetQ3_1: Q3.1(G) R173.1 R177.2

Not connected (* = marked no-connect by the designer): U18 2(NC)* 5(NC)*

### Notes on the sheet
- Design Note
- For Adjustale Regulator Mount
- 2.
- 3.
- 1.
- R119, R121 - WR04X6802FTL
- C100- GJM1555C1H100FB01D
- U19- TPS628502QDRLRQ1
- DC-DC REGULATOR - 1.2V
- R36 - CRCW040240K2FKEDC
- U20- TPS628502QDRLRQ1
- DC-DC REGULATOR - 1.8V
- 4.
- C1- GJM1555C1H100FB01D
- R35 - CRCW040280K6FKEDC
- Design note:- 3.3V LDO enable with 1.8V
- The VCC_3V3 Output from LDO is used as PGOOD

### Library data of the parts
C1 C100 = CMP-0120082-1: Multi-Layer Ceramic Capacitor 10pF C0G  ±1% 0402 Paper T/R; Manufacturer: Murata; AEC Qualified: No; SizeZ_mm: 0.55mm; TempCo: 30ppm/°C; VDC_V: 50V
C61 C79 = CMP-0092150-1: Chip Multilayer Ceramic Capacitors for General Purpose, 1206, 22uF, X7R, 15%, 20%, 6.3V; Manufacturer: Murata; SizeZ_mm: 1.8mm; AEC Qualified: No; Value: 22µF
C62 C72 C119 C120 C128 C129 = CMP-0007295-4: CAP, CERM, 10 uF, 10 V, +/- 20%, X6S, 0603; Manufacturer: MuRata; TaMin_C: -55°C; Polarized: N; SizeAreaWB_mm2: 4.68; Value1: Unknown; U/M: EA; Value: 10uF; TaMax_C: 105°C; SizeZ_mm: 1; SizeX_mm: 1.6; SizeY_mm: 0.8; SizeArea_mm2: 1.28; Cap_F: 10µF; AEC Category: Q200
C66 C73 = CMP-0007398-4: CAP, CERM, 0.47 uF, 16 V, +/- 10%, X7R, 0603; Manufacturer: MuRata; TaMin_C: -55°C; Polarized: N; SizeAreaWB_mm2: 4.68; Value1: Unknown; U/M: EA; Value: 0.47uF; TaMax_C: 125°C; SizeZ_mm: 1; SizeX_mm: 1.6; SizeY_mm: 0.8; Cap_Case: 0603; Value2: 16V; SizeArea_mm2: 1.28; AEC Category: Q200
C67 C74 = CMP-0006470-2: CAP, CERM, 470 pF, 50 V, +/- 5%, C0G/NP0, 0402; Manufacturer: MuRata; TaMin_C: -55°C; Polarized: N; SizeAreaWB_mm2: 3; Value1: Unknown; U/M: EA; Value: 470pF; TaMax_C: 125°C; SizeZ_mm: 0.6; SizeX_mm: 1; SizeY_mm: 0.5; Cap_Case: 0402; Value2: 50V; AEC Category: Q200
C68 = CMP-0008940-2: CAP, CERM, 47 uF, 6.3 V, +/- 20%, X5R, 1206; Manufacturer: MuRata; TaMin_C: -55°C; ESR_ohm: 3m; Polarized: N; SizeAreaWB_mm2: 10.92; Value1: 0.003 ohm; U/M: EA; Value: 47uF; TaMax_C: 85°C; SizeZ_mm: 1.8; SizeX_mm: 3.2; SizeY_mm: 1.6; Cap_Case: 1206; Value2: 6.3V; SizeArea_mm2: 5.12; Cap_F: 47µF; AEC Category: Q200
C69 C70 = CMP-0006526-2: CAP, CERM, 2.2 uF, 16 V, +/- 10%, X6S, 0402; Manufacturer: MuRata; TaMin_C: -55°C; Polarized: N; SizeAreaWB_mm2: 3; Value1: Unknown; U/M: EA; Value: 2.2uF; TaMax_C: 105°C; SizeZ_mm: 0.6; SizeX_mm: 1; SizeY_mm: 0.5; Cap_Case: 0402; Value2: 16V; Cap_F: 2.2µF; AEC Category: Q200
C121 C122 C130 C131 = CMP-0008676-3: CAP, CERM, 22 uF, 10 V, +/- 20%, X6S, 1206; Manufacturer: TDK; TaMin_C: -55°C; ESR_ohm: 2.398m; Polarized: N; SizeAreaWB_mm2: 10.92; Value1: 0.002398 ohm; U/M: EA; Value: 22uF; TaMax_C: 105°C; SizeZ_mm: 1.8; SizeX_mm: 3.2; SizeY_mm: 1.6; Cap_Case: 1206_180; Value2: 10V; SizeArea_mm2: 5.12; Cap_F: 22µF; IRMS_A: 4.6851A; AEC Category: Q200
L1 L5 L6 = CMP-0095018-1: 100nH Shielded Multilayer Inductor 4A 19mOhm Max 0806 (2016 Metric); Manufacturer: Murata; Tolerance_%: 20%; Self Resonant Frequency: 200MHz; Test Frequency: 1MHz; Irms: 4000mA; Shrouded: true; SizeZ_mm: 1.2mm; Value: 0.1uH; AEC Grade: Grade 1; DCR_ohm: 0.019; Material: Ferrite; AEC Qualified: Yes
L14 L15 = CMP-0092096-1: 470nH Shielded Wirewound Inductor 3A 42mOhm Max 0805 (2012 Metric); Manufacturer: Murata; DCR_ohm: 0.042; Shrouded: true; SizeZ_mm: 1mm; Value: 0.47uH; Tolerance_%: 20%; Test Frequency: 1MHz; Isat: 4.4A; AEC Qualified: No; Material: Metal Alloy
Q3 = CMP-0091833-1: N-Channel 20V 250mA (Ta) 500mW (Ta) Surface Mount VESM; Manufacturer: Toshiba; Threshold Vgs Min: 0.35V; QgTyp_nC: 0.34nC @ 4.5V; AEC Qualified: No; Rdson45_ohm: 0.75; TJmax_C: +150°C; Input Capacitace At Vds: 18pF @ 10V; SizeZ_mm: 0.55mm; Pulse Drain Current: 600mA; Threshold Vgs Max: 1V; Vgs_V: 10V; Typ Forward Diode Voltage: 0.8V; VdsMax_V: 1.2V; Power_W: 150mW; Number Of N Channels: 1; Turn Off Delay Time: 6.5ns; ChMode: False; Turn On Delay Time: 2ns
R9 = CMP-0001699-1: 10 kOhms ±1% 0.063W, 1/16W Chip Resistor 0402 (1005 Metric) Moisture Resistant Thick Film; Manufacturer: Yageo; AEC Qualified: No; Power_W: 63mW; SizeZ_mm: 0.4mm; TempCo: 100ppm/°C; VDC_V: 50V
R35 R119 R173 R176 R198 = CMP-0093147-1: Res Jumper Thick Film 0402 0 Ohm 5% 1/16W Molded SMD Paper T/R; Manufacturer: Yageo; AEC Qualified: No; Power_W: 63mW; SizeZ_mm: 0.4mm; VDC_V: 50V
R36 = CMP-0120085-1: 40.2 kOhms ±1% 0.063W, 1/16W Chip Resistor 0402 (1005 Metric) Thick Film; Manufacturer: Vishay; AEC Qualified: No; Power_W: 63mW; SizeZ_mm: 0.35mm; TempCo: 100ppm/°C; VDC_V: 50V; Category 5C6A91606D4187Ad: Resistors; Category 7542B8484461Ae85: Passive Components; Category Cd01000Bfc2916C6: Single Components
R121 = CMP-0120089-1: 68 kOhms ±1% 0.063W, 1/16W Chip Resistor 0402 (1005 Metric) Thick Film; Manufacturer: Walsin Technology; AEC Qualified: No; Power_W: 63mW; SizeZ_mm: 0.4mm; TempCo: 100ppm/°C; VDC_V: 50V
R175 R177 R201 R238 R244 = CMP-0092204-1: 100 kOhms ±1% 0.063W, 1/16W Chip Resistor 0402 (1005 Metric)  Thick Film; Manufacturer: Vishay; Power_W: 63mW; AEC Qualified: No; TempCo: 100ppm/°C; SizeZ_mm: 0.35mm; VDC_V: 50V; Value: 100k
R178 R180 = CMP-0094741-1: Res Thick Film 0402 18K Ohm 1% 1/16W ±100ppm/°C Molded SMD Paper T/R; Manufacturer: Vishay; VDC_V: 50V; SizeZ_mm: 0.35mm; AEC Qualified: No; Power_W: 63mW
TP9 TP11 = CMP-0078143-3: TEST POINT.  No entry in BOM.
U18 = CMP-0013427-7: 500mA LDO, DRV0006A (WSON-6); Manufacturer: Texas Instruments; SizeX_mm: 2; CompType: IC; SizeZ_mm: 0.8; SizeArea_mm2: 4; SizeAreaWB_mm2: 9; U/M: EA
U19 = CMP-0120067-1: 2.7-V to 6-V, 2-A Step-Down Converter in SOT583 Package; Manufacturer: Texas Instruments; SizeZ_mm: 0.6mm; AEC Qualified: No; Max Duty Cycle: 100%; Max Supply Voltage: 6V; Min Supply Voltage: 2.7V; Nominal Supply Current: 17uA; Number Of Outputs: 1; Output Type: AdjustableProgrammable; Output Voltage: 0.6-5.5V; Standoff Height: 0mm; Switching Frequency: 1.8-4MHz; Switching Topology: Buck; TJmax_C: +150°C
U20 = CMP-0120069-1: 2.7-V to 6-V, 2-A Step-Down Converter in SOT583 Package; Manufacturer: Texas Instruments; SizeZ_mm: 0.6mm; AEC Qualified: No; Max Duty Cycle: 100%; Max Supply Voltage: 6V; Min Supply Voltage: 2.7V; Nominal Supply Current: 17uA; Number Of Outputs: 1; Output Type: AdjustableProgrammable; Output Voltage: 0.6-5.5V; Standoff Height: 0mm; Switching Frequency: 1.8-4MHz; Switching Topology: Buck; TJmax_C: +150°C

## Sheet PROC177B_xWRL6432AoP_Chip.SchDoc: xWRL6432AOP_CHIP
size 431 x 279 mm; Date: Not shown in title block; ApprovedBy: Not shown in title block; CheckedBy: Not shown in title block; Author: Not shown in title block; CompanyName: Not shown in title block; DrawnBy: Mistral; Engineer: Not shown in title block; Organization: Not shown in title block; Address1: Not shown in title block; Address2: Not shown in title block; Address3: Not shown in title block; Address4: Not shown in title block; DocumentNumber: 6; Revision: Use project parameter SCH_Rev; SheetNumber: 6; SheetTotal: 17; PageSetup: Record=PageOptions¦CenterHorizontal=True¦CenterVertical=True¦PrintScale=1.00¦XCorrection=1.00¦YCorrection=1.00¦PrintKind=0¦BorderSize=5000000¦LeftOffset=0¦BottomOffset=0¦Orientation=2¦PaperLength=1000¦PaperWidth=1000¦Scale=100¦PaperSource=15¦PrintQuality=600¦MediaType=1¦DitherType=10¦PaperKind=Letter¦PrintScaleMode=1
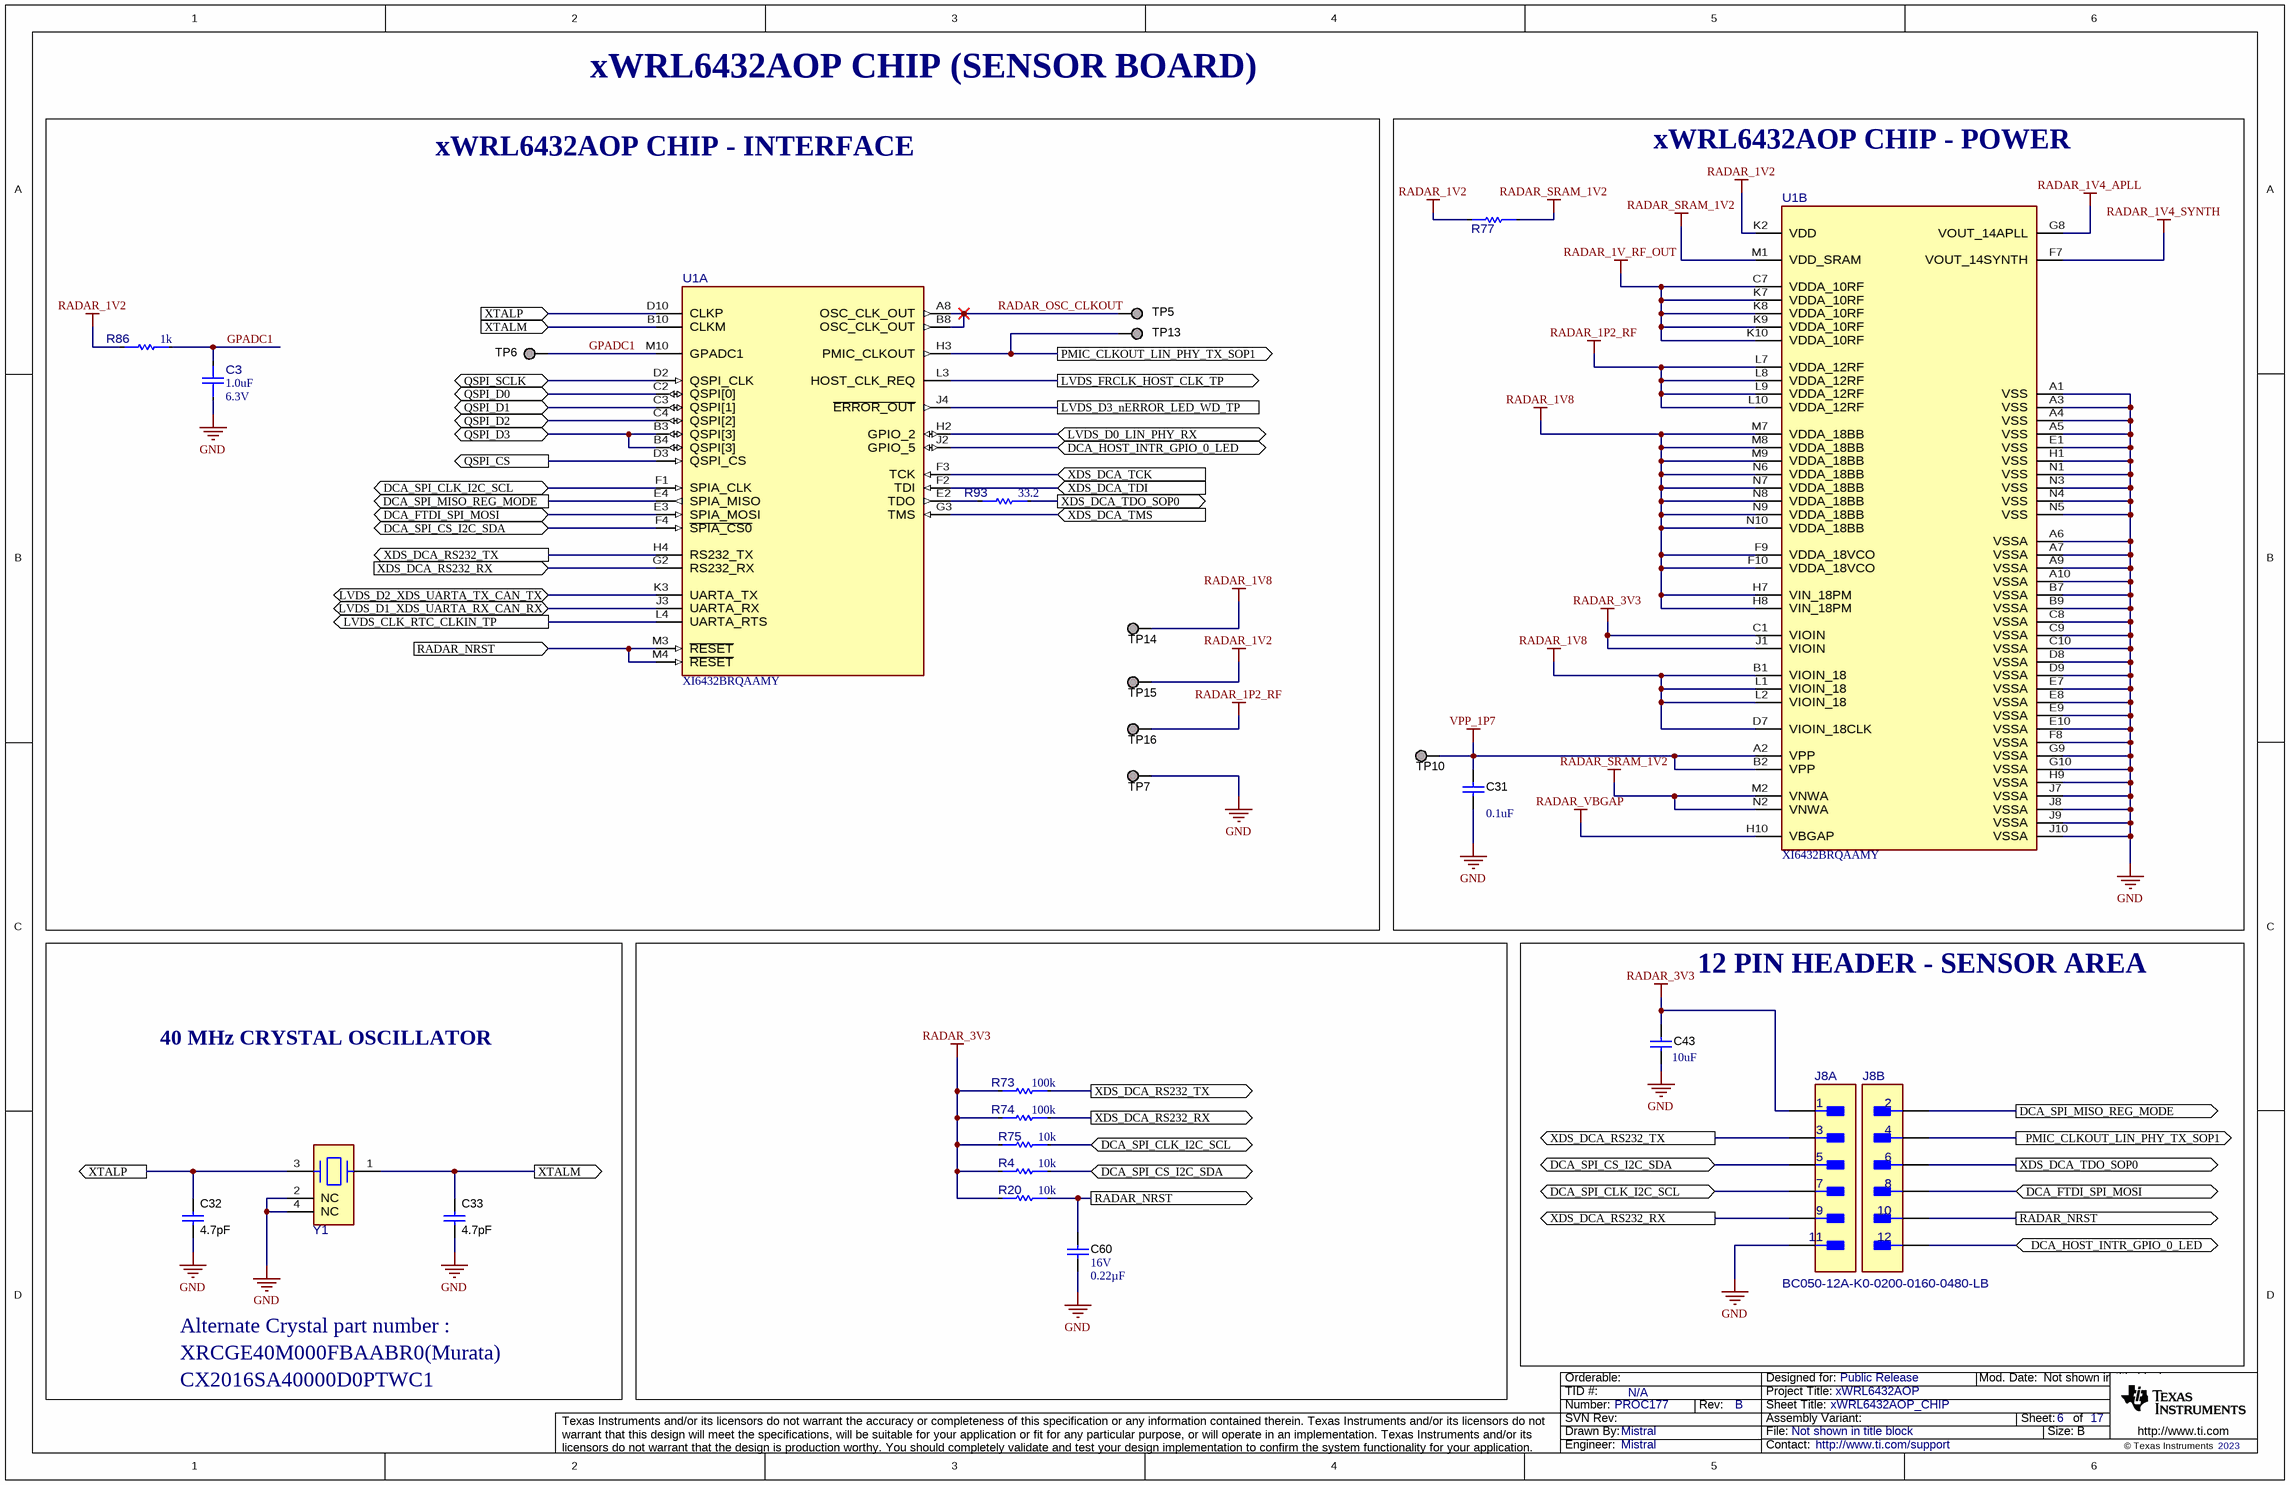
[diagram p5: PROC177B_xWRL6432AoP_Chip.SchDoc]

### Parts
C3  ValueDisplayed: 1.0uF  VDC_V: 6.3V  [FP-GRM155C80J105KA12D_0402-MFG]  (hidden comment: GRM155C80J105KA12D)
C31  ValueDisplayed: 0.1uF  [0402]  (hidden comment: C1005X7R1H104K050BE)
C32  ValueDisplayed: 4.7pF  [0402L]  (hidden comment: GJM1555C1H4R7BB01D)
C33  ValueDisplayed: 4.7pF  [0402L]  (hidden comment: GJM1555C1H4R7BB01D)
C43  ValueDisplayed: 10uF  [0603L]  (hidden comment: GRM188C81A106MA73D)
C60  VDC_V: 16V  ValueDisplayed: 0.22µF  [0402L]  (hidden comment: CL05B224KO5NNNC)
J8  BC050-12A-K0-0200-0160-0480-LB  [FP-BC050-12A-K0-0200-0160-0480-LB_HDR12-MFG]  (parts A,B of 2)
R4  value 10k  [FP-RC0402FR-0710KL_0402-IPC_B]  (hidden comment: RC0402FR-0710KL)
R20  value 10k  [FP-RC0402FR-0710KL_0402-IPC_B]  (hidden comment: RC0402FR-0710KL)
R73  value 100k  [FP-WR04X1003FTL_0402-IPC_B]  (hidden comment: WR04X1003FTL)
R74  value 100k  [FP-WR04X1003FTL_0402-IPC_B]  (hidden comment: WR04X1003FTL)
R75  value 10k  [FP-RC0402FR-0710KL_0402-IPC_B]  (hidden comment: RC0402FR-0710KL)
R77  RC0402JR-070RP  [FP-RC0402JR-070RP_0402-MFG]  (value not drawn)
R86  value 1k  [FP-RC0402FR-071KL_0402-IPC_B]  (hidden comment: RC0402FR-071KL)
R93  value 33.2  [FP-RT0402FRE0733R2L_0402-MFG]  (hidden comment: RT0402FRE0733R2L)
TP5  TESTPOINT  [TP_25MIL-SMT]  (value not drawn)  (no BOM)
TP6  TESTPOINT  [TP_25MIL-SMT]  (value not drawn)  (no BOM)
TP7  TESTPOINT  [TP_25MIL-SMT]  (value not drawn)  (no BOM)
TP10  TP_SM_1MM  [TP_SM_1MM]  (value not drawn)  (no BOM)
TP13  TESTPOINT  [TP_25MIL-SMT]  (value not drawn)  (no BOM)
TP14  TESTPOINT  [TP_25MIL-SMT]  (value not drawn)  (no BOM)
TP15  TESTPOINT  [TP_25MIL-SMT]  (value not drawn)  (no BOM)
TP16  TESTPOINT  [TP_25MIL-SMT]  (value not drawn)  (no BOM)
U1  XI6432BRQAAMY  [AMY0101A-MFG]  (parts A,B of 2)
Y1  XRCGB40M000F1S2GR0  [FP-XRCGB40M000F1S2GR0_SMT_CRYSTAL_2MM0_1MM6-MFG]  (value not drawn)

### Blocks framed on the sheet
xWRL6432AOP CHIP - INTERFACE: C3 R86 R93 TP5-TP7 TP13-TP16 U1
xWRL6432AOP CHIP - POWER: C31 R77 TP10 U1
12 PIN HEADER - SENSOR AREA: C43 J8

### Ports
DCA_FTDI_SPI_MOSI (bidir), DCA_HOST_INTR_GPIO_0_LED (bidir), DCA_SPI_CLK_I2C_SCL (bidir), DCA_SPI_CS_I2C_SDA (bidir), DCA_SPI_MISO_REG_MODE (out), LVDS_CLK_RTC_CLKIN_TP (out), LVDS_D0_LIN_PHY_RX (bidir), LVDS_D1_XDS_UARTA_RX_CAN_RX (bidir), LVDS_D2_XDS_UARTA_TX_CAN_TX (bidir), LVDS_D3_nERROR_LED_WD_TP, LVDS_FRCLK_HOST_CLK_TP (out), PMIC_CLKOUT_LIN_PHY_TX_SOP1 (out), QSPI_CS (out), QSPI_D0 (bidir), QSPI_D1 (bidir), QSPI_D2 (bidir), QSPI_D3 (bidir), QSPI_SCLK (bidir), RADAR_NRST (in), RADAR_NRST (out), XDS_DCA_RS232_RX (in), XDS_DCA_RS232_RX (out), XDS_DCA_RS232_TX (out), XDS_DCA_TCK (in), XDS_DCA_TDI (in), XDS_DCA_TDO_SOP0 (out), XDS_DCA_TMS (in), XTALM (in), XTALM (out), XTALP (in), XTALP (out)

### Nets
GND: C3.1 C31.2 C32.1 C33.1 C43.2 C60.1 J8.11 TP7.1 U1.A1(VSS) U1.A3(VSS) U1.A4(VSS) U1.A5(VSS) U1.A6(VSSA) U1.A7(VSSA) U1.A9(VSSA) U1.A10(VSSA) U1.B7(VSSA) U1.B9(VSSA) U1.C8(VSSA) U1.C9(VSSA) U1.C10(VSSA) U1.D8(VSSA) U1.D9(VSSA) U1.E1(VSS) U1.E7(VSSA) U1.E8(VSSA) U1.E9(VSSA) U1.E10(VSSA) U1.F8(VSSA) U1.G9(VSSA) U1.G10(VSSA) U1.H1(VSS) U1.H9(VSSA) U1.J7(VSSA) U1.J8(VSSA) U1.J9(VSSA) U1.J10(VSSA) U1.N1(VSS) U1.N3(VSS) U1.N4(VSS) U1.N5(VSS) Y1.2(NC) Y1.4(NC)
RADAR_1P2_RF: TP16.1 U1.L7(VDDA_12RF) U1.L8(VDDA_12RF) U1.L9(VDDA_12RF) U1.L10(VDDA_12RF)
RADAR_1V2: R77.2 R86.2 TP15.1 U1.K2(VDD)
RADAR_1V4_APLL: U1.G8(VOUT_14APLL)
RADAR_1V4_SYNTH: U1.F7(VOUT_14SYNTH)
RADAR_1V8: TP14.1 U1.B1(VIOIN_18) U1.D7(VIOIN_18CLK) U1.F9(VDDA_18VCO) U1.F10(VDDA_18VCO) U1.H7(VIN_18PM) U1.H8(VIN_18PM) U1.L1(VIOIN_18) U1.L2(VIOIN_18) U1.M7(VDDA_18BB) U1.M8(VDDA_18BB) U1.M9(VDDA_18BB) U1.N6(VDDA_18BB) U1.N7(VDDA_18BB) U1.N8(VDDA_18BB) U1.N9(VDDA_18BB) U1.N10(VDDA_18BB)
RADAR_1V_RF_OUT: U1.C7(VDDA_10RF) U1.K7(VDDA_10RF) U1.K8(VDDA_10RF) U1.K9(VDDA_10RF) U1.K10(VDDA_10RF)
RADAR_3V3: C43.1 J8.1 R4.2 R20.2 R73.2 R74.2 R75.2 U1.C1(VIOIN) U1.J1(VIOIN)
RADAR_SRAM_1V2: R77.1 U1.M1(VDD_SRAM) U1.M2(VNWA) U1.N2(VNWA)
RADAR_VBGAP: U1.H10(VBGAP)
VPP_1P7: C31.1 TP10.1 U1.A2(VPP) U1.B2(VPP)
DCA_FTDI_SPI_MOSI: J8.8 U1.E3(SPIA_MOSI) ; port DCA_FTDI_SPI_MOSI
DCA_HOST_INTR_GPIO_0_LED: J8.12 U1.J2(GPIO_5) ; port DCA_HOST_INTR_GPIO_0_LED
DCA_SPI_CLK_I2C_SCL: J8.7 R75.1 U1.F1(SPIA_CLK) ; port DCA_SPI_CLK_I2C_SCL
DCA_SPI_CS_I2C_SDA: J8.5 R4.1 U1.F4(~{SPIA_CS0}) ; port DCA_SPI_CS_I2C_SDA
DCA_SPI_MISO_REG_MODE: J8.2 U1.E4(SPIA_MISO) ; port DCA_SPI_MISO_REG_MODE
GPADC1: C3.2 R86.1 TP6.1 U1.M10(GPADC1)
LVDS_CLK_RTC_CLKIN_TP: U1.L4(UARTA_RTS) ; port LVDS_CLK_RTC_CLKIN_TP
LVDS_D0_LIN_PHY_RX: U1.H2(GPIO_2) ; port LVDS_D0_LIN_PHY_RX
LVDS_D1_XDS_UARTA_RX_CAN_RX: U1.J3(UARTA_RX) ; port LVDS_D1_XDS_UARTA_RX_CAN_RX
LVDS_D2_XDS_UARTA_TX_CAN_TX: U1.K3(UARTA_TX) ; port LVDS_D2_XDS_UARTA_TX_CAN_TX
LVDS_D3_nERROR_LED_WD_TP: U1.J4(~{ERROR_OUT}) ; port LVDS_D3_nERROR_LED_WD_TP
LVDS_FRCLK_HOST_CLK_TP: U1.L3(HOST_CLK_REQ) ; port LVDS_FRCLK_HOST_CLK_TP
PMIC_CLKOUT_LIN_PHY_TX_SOP1: J8.4 TP13.1 U1.H3(PMIC_CLKOUT) ; port PMIC_CLKOUT_LIN_PHY_TX_SOP1
QSPI_CS: U1.D3(QSPI_CS) ; port QSPI_CS
QSPI_D0: U1.C2(QSPI[0]) ; port QSPI_D0
QSPI_D1: U1.C3(QSPI[1]) ; port QSPI_D1
QSPI_D2: U1.C4(QSPI[2]) ; port QSPI_D2
QSPI_D3: U1.B3(QSPI[3]) U1.B4(QSPI[3]) ; port QSPI_D3
QSPI_SCLK: U1.D2(QSPI_CLK) ; port QSPI_SCLK
RADAR_NRST: C60.2 J8.10 R20.1 U1.M3(~{RESET}) U1.M4(~{RESET}) ; port RADAR_NRST
RADAR_OSC_CLKOUT: TP5.1 U1.A8(OSC_CLK_OUT) U1.B8(OSC_CLK_OUT)
XDS_DCA_RS232_RX: J8.9 R74.1 U1.G2(RS232_RX) ; port XDS_DCA_RS232_RX
XDS_DCA_RS232_TX: J8.3 R73.1 U1.H4(RS232_TX) ; port XDS_DCA_RS232_TX
XDS_DCA_TCK: U1.F3(TCK) ; port XDS_DCA_TCK
XDS_DCA_TDI: U1.F2(TDI) ; port XDS_DCA_TDI
XDS_DCA_TDO_SOP0: J8.6 R93.1 ; port XDS_DCA_TDO_SOP0
XDS_DCA_TMS: U1.G3(TMS) ; port XDS_DCA_TMS
XTALM: C33.2 U1.B10(CLKM) Y1.1 ; port XTALM
XTALP: C32.2 U1.D10(CLKP) Y1.3 ; port XTALP
NetR93_2: R93.2 U1.E2(TDO)

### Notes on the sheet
- xWRL6432AOP CHIP (SENSOR BOARD)
- 40 MHz CRYSTAL OSCILLATOR
- Alternate Crystal part number :
- XRCGE40M000FBAABR0(Murata)
- CX2016SA40000D0PTWC1

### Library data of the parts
C3 = CMP-0120013-1: Chip Multilayer Ceramic Capacitors for General Purpose, 0402, 1.0uF, X6S, 22%, 10%, 6.3V; Manufacturer: Murata; AEC Qualified: No; Cap_F: 1µF; SizeZ_mm: 0.55mm; Value: 1µF
C31 = CMP-0064946-2: CAP, CERM, 0.1 uF, 50 V,+/- 10%, X7R, 0402; Manufacturer: TDK; TaMin_C: -55°C; Polarized: N; SizeAreaWB_mm2: 3; Value1: Unknown; U/M: EA; Value: 0.1uF; TaMax_C: 125°C; SizeZ_mm: 0.6; SizeX_mm: 1; SizeY_mm: 0.5; Value2: 50V; Cap_F: 100nF; AEC Category: Q200
C32 C33 = CMP-0006367-2: CAP, CERM, 4.7 pF, 50 V, +/- 2%, C0G/NP0, 0402; Manufacturer: MuRata; TaMin_C: -55°C; Polarized: N; SizeAreaWB_mm2: 3; Value1: Unknown; U/M: EA; Value: 4.7pF; TaMax_C: 125°C; SizeZ_mm: 0.6; SizeX_mm: 1; SizeY_mm: 0.5; Cap_Case: 0402; Value2: 50V; CompType: Capacitor; AEC Category: Q200
C43 = CMP-0007295-4: CAP, CERM, 10 uF, 10 V, +/- 20%, X6S, 0603; Manufacturer: MuRata; TaMin_C: -55°C; Polarized: N; SizeAreaWB_mm2: 4.68; Value1: Unknown; U/M: EA; Value: 10uF; TaMax_C: 105°C; SizeZ_mm: 1; SizeX_mm: 1.6; SizeY_mm: 0.8; Cap_Case: 0603; Value2: 10V; SizeArea_mm2: 1.28; Cap_F: 10µF; AEC Category: Q200
C60 = CMP-0860563-1: CAP, CERM, 0.22 µF, 16 V,+/- 10%, X7R, 0402; Manufacturer: Samsung Electro-Mechanics; SizeX_mm: 1; Cap_Case: 0402; Green_REACh: Incomplete; TaMin_C: -55°C; SizeArea_mm2: 0.5; TaMax_C: 125°C; U/M: EA; Green_Lifecycle: Active; SizeAreaWB_mm2: 3; AEC Qualified: N; SizeZ_mm: 0.6; AEC Category: Q200; Cap_F: 220nF; Value: 0.22uF
J8 = CMP-0049921-1: Manufacturer: GCT; ContactFinish: Gold,Nickel; Current_A: 1A; Row_Count: 2; Voltage_V: 250V; AEC Qualified: No; Conn Gender: Male; Conn Orientation: Straight; DUT-Pitch_mm: 1mm; SizeZ_mm: 4.1mm
R4 R20 R75 = CMP-0001699-1: as R9 on sheet PROC177B_DC_Regulators
R73 R74 = CMP-0120018-1: 100 kOhms ±1% 0.063W, 1/16W Chip Resistor 0402 (1005 Metric) Thick Film; Manufacturer: Walsin Technology; AEC Qualified: No; Power_W: 63mW; SizeZ_mm: 0.4mm; TempCo: 100ppm/°C; VDC_V: 50V
R77 = CMP-0093147-1: Res Jumper Thick Film 0402 0 Ohm 5% 1/16W Molded SMD Paper T/R; Manufacturer: Yageo; AEC Qualified: No; Power_W: 63mW; Res_ohm: 0; Value: 0; SizeZ_mm: 0.4mm; VDC_V: 50V
R86 = CMP-0098279-1: RES Thick Film SMD 1kΩ 1% 1/16W 0402 100ppm/°C; Manufacturer: Yageo; AEC Qualified: No; Power_W: 63mW; SizeZ_mm: 0.4mm; VDC_V: 50V; Standoff Height: 0mm
R93 = CMP-0120016-1: 33.2 Ohms ±1% 0.063W, 1/16W Chip Resistor 0402 (1005 Metric) Thin Film; Manufacturer: Yageo; AEC Qualified: No; Power_W: 63mW; SizeZ_mm: 0.35mm; TempCo: 50ppm/°C; VDC_V: 50V
TP5-TP7 TP13-TP16 = CMP-0078143-3: TEST POINT.  No entry in BOM.
TP10 = CMP-0003825-1: 1mm Test Point, SMT; Manufacturer: Any
U1 = CMP-0120794-2: Manufacturer: Texas Instruments; SizeZ_mm: 0.757mm; Standoff Height: 0.219mm; AEC Category: Q200; CompType: IC
Y1 = CMP-0120019-1: Crystal Resonator 40MHz ±10ppm (Tol) ±20ppm (Stability) 8pF 50Ohm 4-Pin SMD T/R; Manufacturer: Murata; SizeZ_mm: 0.7mm; AEC Qualified: No; Esr: 50

## Sheet PROC177B_Decoupling_caps_QSPI_Flash_.SchDoc: DECOUPLING_CAPS_QSPI FLASH
size 431 x 279 mm; Date: Not shown in title block; ApprovedBy: Not shown in title block; CheckedBy: Not shown in title block; Author: Not shown in title block; CompanyName: Not shown in title block; DrawnBy: Mistral; Engineer: Not shown in title block; Organization: Not shown in title block; Address1: Not shown in title block; Address2: Not shown in title block; Address3: Not shown in title block; Address4: Not shown in title block; DocumentNumber: 7; Revision: Use project parameter SCH_Rev; SheetNumber: 7; SheetTotal: 17; PageSetup: Record=PageOptions¦CenterHorizontal=True¦CenterVertical=True¦PrintScale=1.00¦XCorrection=1.00¦YCorrection=1.00¦PrintKind=0¦BorderSize=5000000¦LeftOffset=0¦BottomOffset=0¦Orientation=2¦PaperLength=1000¦PaperWidth=1000¦Scale=100¦PaperSource=15¦PrintQuality=600¦MediaType=1¦DitherType=10¦PaperKind=Letter¦PrintScaleMode=1
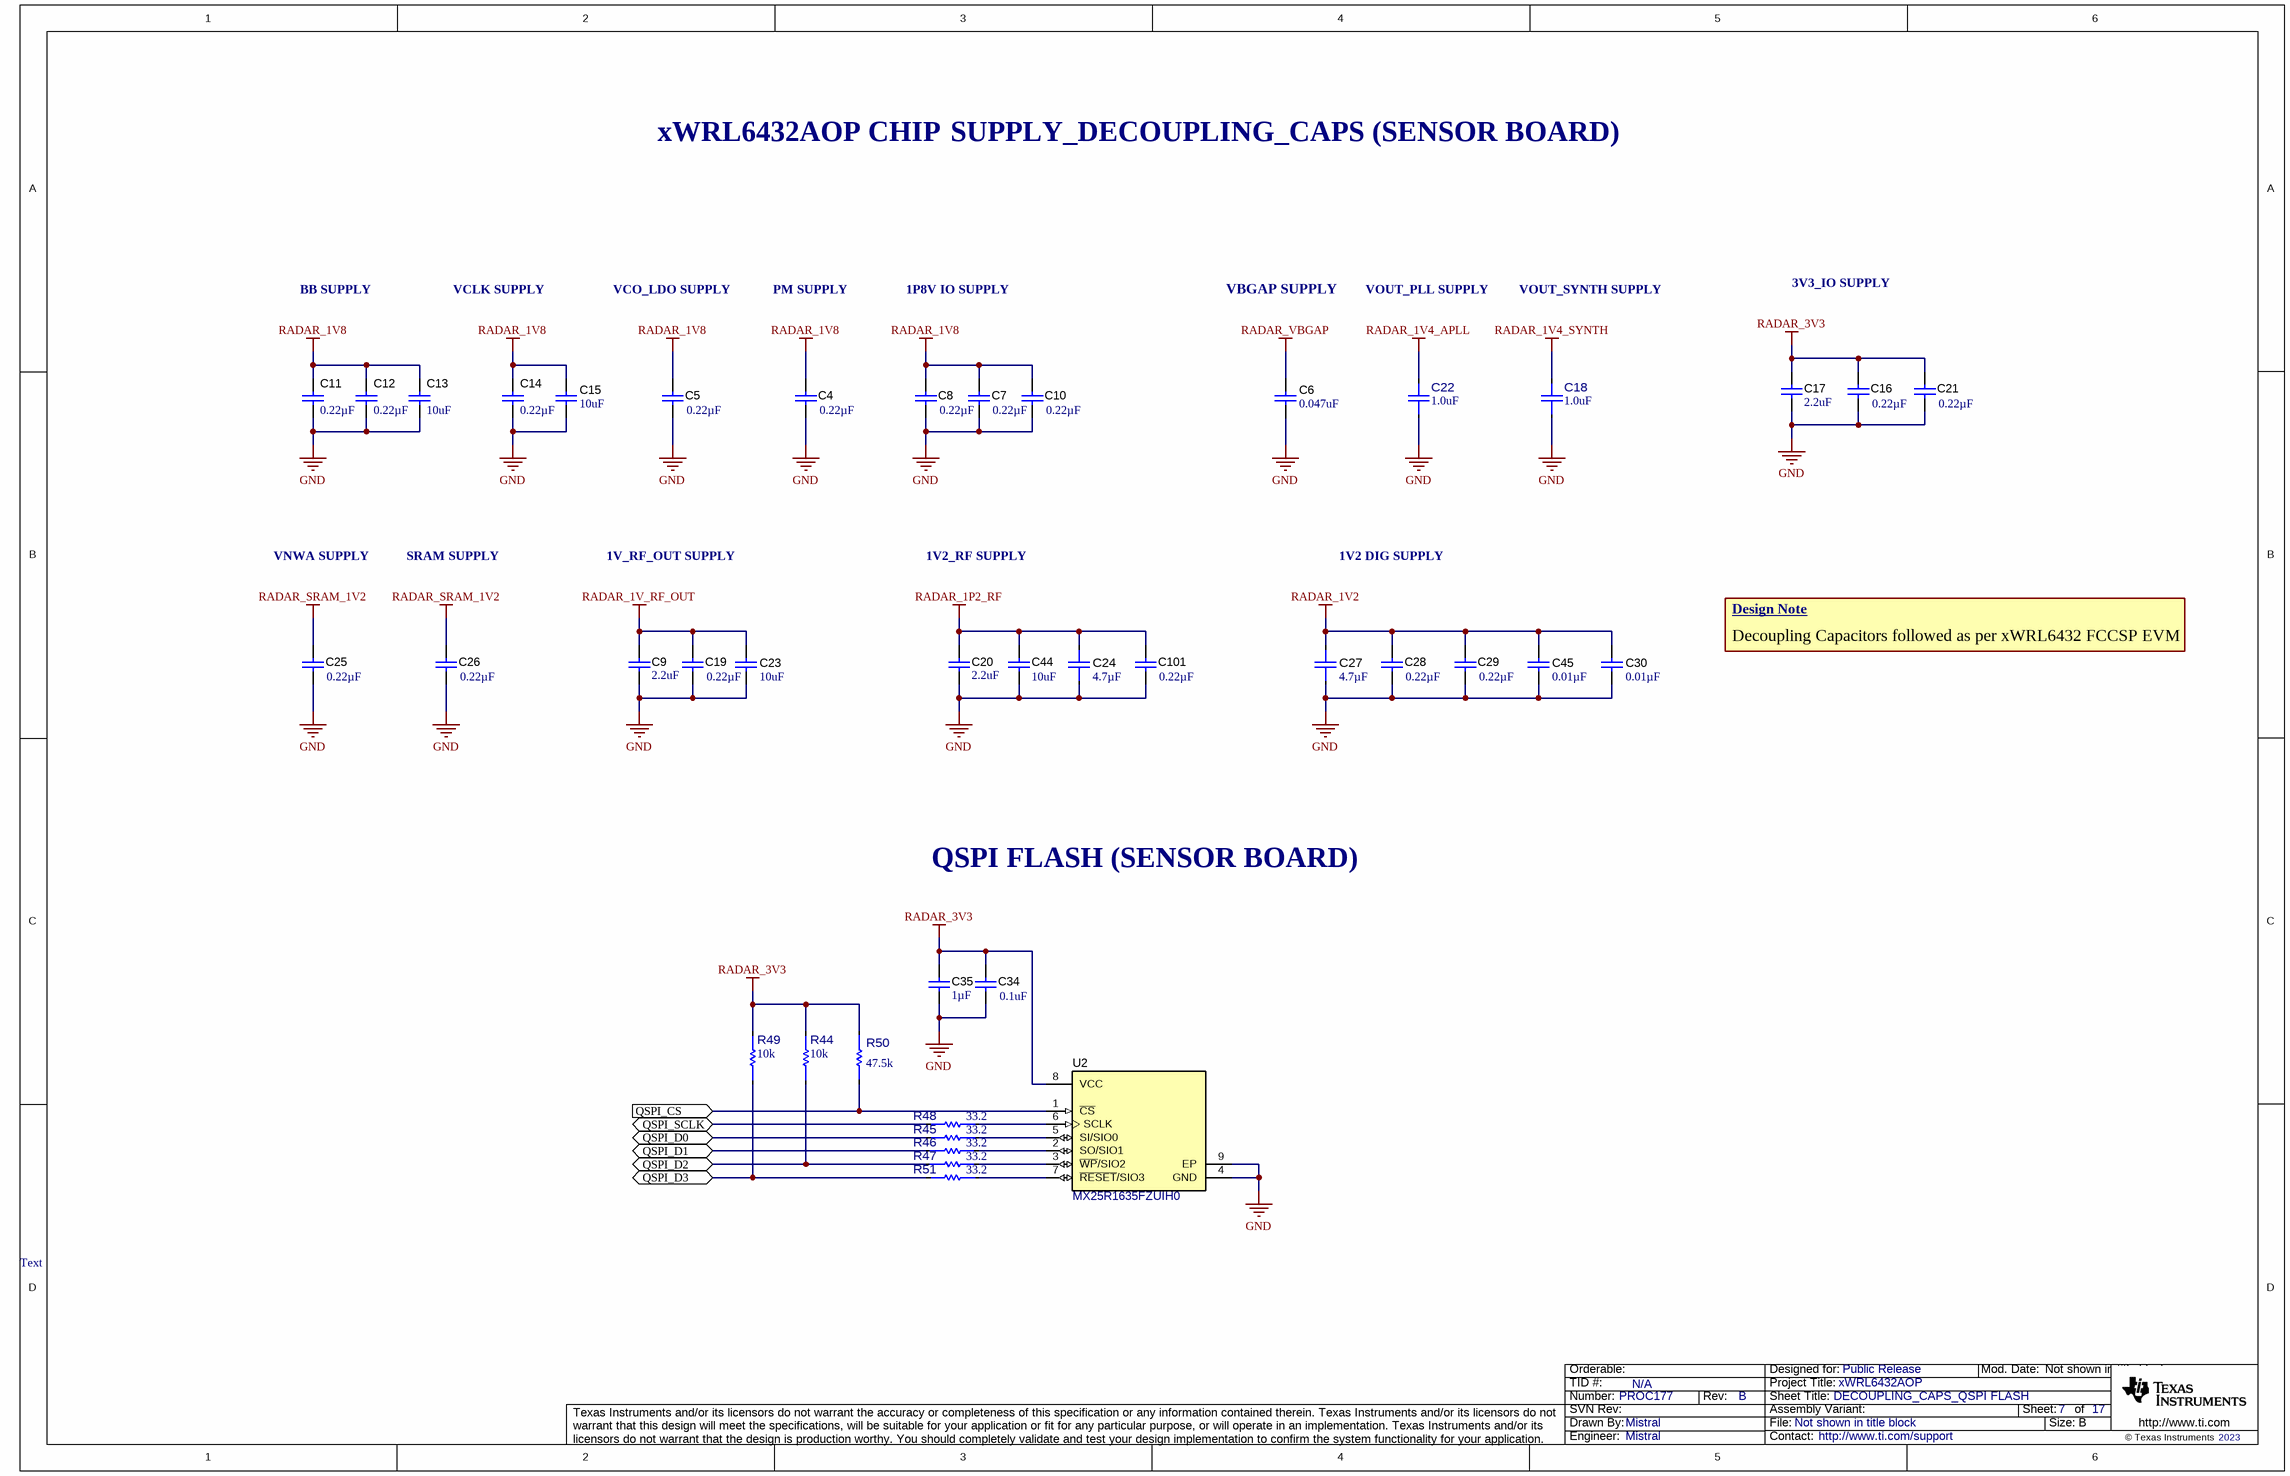
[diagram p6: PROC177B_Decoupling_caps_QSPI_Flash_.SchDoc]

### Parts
C4  ValueDisplayed: 0.22µF  [0402L]  (hidden comment: CL05B224KO5NNNC)
C5  ValueDisplayed: 0.22µF  [0402L]  (hidden comment: CL05B224KO5NNNC)
C6  ValueDisplayed: 0.047uF  [0402L]  (hidden comment: C1005X7R1H473K050BB)
C7  ValueDisplayed: 0.22µF  [0402L]  (hidden comment: CL05B224KO5NNNC)
C8  ValueDisplayed: 0.22µF  [0402L]  (hidden comment: CL05B224KO5NNNC)
C9  ValueDisplayed: 2.2uF  [0402S]  (hidden comment: GRM155C81C225KE11D)
C10  ValueDisplayed: 0.22µF  [0402L]  (hidden comment: CL05B224KO5NNNC)
C11  ValueDisplayed: 0.22µF  [0402L]  (hidden comment: CL05B224KO5NNNC)
C12  ValueDisplayed: 0.22µF  [0402L]  (hidden comment: CL05B224KO5NNNC)
C13  ValueDisplayed: 10uF  [0603L]  (hidden comment: GRM188C81A106MA73D)
C14  ValueDisplayed: 0.22µF  [0402L]  (hidden comment: CL05B224KO5NNNC)
C15  ValueDisplayed: 10uF  [0603L]  (hidden comment: GRM188C81A106MA73D)
C16  ValueDisplayed: 0.22µF  [0402L]  (hidden comment: CL05B224KO5NNNC)
C17  ValueDisplayed: 2.2uF  [0402S]  (hidden comment: GRM155C81C225KE11D)
C18  ValueDisplayed: 1.0uF  [FP-GRM155C80J105KA12D_0402-MFG]  (hidden comment: GRM155C80J105KA12D)
C19  ValueDisplayed: 0.22µF  [0402L]  (hidden comment: CL05B224KO5NNNC)
C20  ValueDisplayed: 2.2uF  [0402S]  (hidden comment: GRM155C81C225KE11D)
C21  ValueDisplayed: 0.22µF  [0402L]  (hidden comment: CL05B224KO5NNNC)
C22  ValueDisplayed: 1.0uF  [FP-GRM155C80J105KA12D_0402-MFG]  (hidden comment: GRM155C80J105KA12D)
C23  ValueDisplayed: 10uF  [0603L]  (hidden comment: GRM188C81A106MA73D)
C24  Cap_F: 4.7µF  [FP-GRM21BR71C475KE51L_0805-MFG]  (hidden comment: GRM21BR71C475KE51L)
C25  ValueDisplayed: 0.22µF  [0402L]  (hidden comment: CL05B224KO5NNNC)
C26  ValueDisplayed: 0.22µF  [0402L]  (hidden comment: CL05B224KO5NNNC)
C27  value 4.7µF  [FP-GRM21BR71C475KE51L_0805-MFG]  (hidden comment: GRM21BR71C475KE51L)
C28  ValueDisplayed: 0.22µF  [0402L]  (hidden comment: CL05B224KO5NNNC)
C29  ValueDisplayed: 0.22µF  [0402L]  (hidden comment: CL05B224KO5NNNC)
C30  ValueDisplayed: 0.01µF  [0402L]  (hidden comment: C0402C103K4RACTU)
C34  ValueDisplayed: 0.1uF  [0402]  (hidden comment: C1005X7R1H104K050BE)
C35  Cap_F: 1µF  [0603]  (hidden comment: CL10B105KO8NFNC)
C44  ValueDisplayed: 10uF  [0603L]  (hidden comment: GRM188C81A106MA73D)
C45  ValueDisplayed: 0.01µF  [0402L]  (hidden comment: C0402C103K4RACTU)
C101  ValueDisplayed: 0.22µF  [0402L]  (hidden comment: CL05B224KO5NNNC)
R44  value 10k  [FP-RC0402FR-0710KL_0402-IPC_B]  (hidden comment: RC0402FR-0710KL)
R45  value 33.2  [FP-RT0402FRE0733R2L_0402-MFG]  (hidden comment: RT0402FRE0733R2L)
R46  value 33.2  [FP-RT0402FRE0733R2L_0402-MFG]  (hidden comment: RT0402FRE0733R2L)
R47  value 33.2  [FP-RT0402FRE0733R2L_0402-MFG]  (hidden comment: RT0402FRE0733R2L)
R48  value 33.2  [FP-RT0402FRE0733R2L_0402-MFG]  (hidden comment: RT0402FRE0733R2L)
R49  value 10k  [FP-RC0402FR-0710KL_0402-IPC_B]  (hidden comment: RC0402FR-0710KL)
R50  value 47.5k  [FP-RC0402FR-1047K5L_0402-MFG]  (hidden comment: RC0402FR-1047K5L)
R51  value 33.2  [FP-RT0402FRE0733R2L_0402-MFG]  (hidden comment: RT0402FRE0733R2L)
U2  MX25R1635FZUIH0  [USON-8L]

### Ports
QSPI_CS (in), QSPI_D0 (bidir), QSPI_D1 (bidir), QSPI_D2 (bidir), QSPI_D3 (bidir), QSPI_SCLK (bidir)

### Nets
GND: C4.1 C5.1 C6.2 C7.1 C8.1 C9.1 C10.1 C11.1 C12.1 C13.2 C14.1 C15.2 C16.1 C17.1 C18.1 C19.1 C20.1 C21.1 C22.1 C23.2 C24.1 C25.1 C26.1 C27.1 C28.1 C29.1 C30.2 C34.2 C35.1 C44.2 C45.2 C101.1 U2.4(GND) U2.9(EP)
RADAR_1P2_RF: C20.2 C24.2 C44.1 C101.2
RADAR_1V2: C27.2 C28.2 C29.2 C30.1 C45.1
RADAR_1V4_APLL: C22.2
RADAR_1V4_SYNTH: C18.2
RADAR_1V8: C4.2 C5.2 C7.2 C8.2 C10.2 C11.2 C12.2 C13.1 C14.2 C15.1
RADAR_1V_RF_OUT: C9.2 C19.2 C23.1
RADAR_3V3: C16.2 C17.2 C21.2 C34.1 C35.2 R44.2 R49.2 R50.1 U2.8(VCC)
RADAR_SRAM_1V2: C25.2 C26.2
RADAR_VBGAP: C6.1
QSPI_CS: R50.2 U2.1(~{CS}) ; port QSPI_CS
QSPI_D0: R45.2 ; port QSPI_D0
QSPI_D1: R46.1 ; port QSPI_D1
QSPI_D2: R44.1 R47.1 ; port QSPI_D2
QSPI_D3: R49.1 R51.2 ; port QSPI_D3
QSPI_SCLK: R48.2 ; port QSPI_SCLK
NetR45_1: R45.1 U2.5(SI/SIO0)
NetR46_2: R46.2 U2.2(SO/SIO1)
NetR47_2: R47.2 U2.3(~{WP}/SIO2)
NetR48_1: R48.1 U2.6(SCLK)
NetR51_1: R51.1 U2.7(~{RESET}/SIO3)

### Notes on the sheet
- xWRL6432AOP CHIP
- SUPPLY_DECOUPLING_CAPS (SENSOR BOARD)
- BB SUPPLY
- VCLK SUPPLY
- VCO_LDO SUPPLY
- PM SUPPLY
- 1P8V IO SUPPLY
- VBGAP SUPPLY
- VOUT_PLL SUPPLY
- VOUT_SYNTH SUPPLY
- 3V3_IO SUPPLY
- VNWA SUPPLY
- SRAM SUPPLY
- 1V_RF_OUT SUPPLY
- 1V2_RF SUPPLY
- 1V2 DIG SUPPLY
- Design Note
- Decoupling Capacitors followed as per xWRL6432 FCCSP EVM
- QSPI FLASH (SENSOR BOARD)
- Text

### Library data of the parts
C4 C5 C7 C8 C10-C12 C14 C16 C19 C21 C25 C26 C28 C29 C101 = CMP-0860563-1: CAP, CERM, 0.22 µF, 16 V,+/- 10%, X7R, 0402; Manufacturer: Samsung Electro-Mechanics; SizeX_mm: 1; Cap_Case: 0402; Green_REACh: Incomplete; TaMin_C: -55°C; SizeArea_mm2: 0.5; TaMax_C: 125°C; U/M: EA; Green_Lifecycle: Active; SizeAreaWB_mm2: 3; VDC_V: 16V; AEC Qualified: N; SizeZ_mm: 0.6; AEC Category: Q200; Cap_F: 220nF; Value: 0.22uF
C6 = CMP-0006298-2: CAP, CERM, 0.047 uF, 50 V, +/- 10%, X7R, 0402; Manufacturer: TDK; TaMin_C: -55°C; ESR_ohm: 64.07m; Polarized: N; SizeAreaWB_mm2: 3; Value1: 0.06407 ohm; U/M: EA; SizeZ_mm: 0.6; SizeX_mm: 1; SizeY_mm: 0.5; Cap_Case: 0402; Value2: 50V; Cap_F: 47nF; IRMS_A: 646.122mA; AEC Category: Q200; TaMax_C: 125°C
C9 C17 C20 = CMP-0006526-2: as C69 on sheet PROC177B_DC_Regulators
C13 C15 C23 C44 = CMP-0007295-4: as C43 on sheet PROC177B_xWRL6432AoP_Chip
C18 C22 = CMP-0120013-1: as C3 on sheet PROC177B_xWRL6432AoP_Chip
C24 = CMP-0120021-1: Chip Multilayer Ceramic Capacitors for General Purpose, 0805, 4.7uF, X7R, 15%, 10%, 16V; Manufacturer: Murata; AEC Qualified: No; SizeZ_mm: 1.4mm; Value: 4.7µF
C27 = CMP-0120021-1: Chip Multilayer Ceramic Capacitors for General Purpose, 0805, 4.7uF, X7R, 15%, 10%, 16V; Manufacturer: Murata; AEC Qualified: No; SizeZ_mm: 1.4mm
C30 C45 = CMP-0078218-1: CAP, CERM, 0.01 µF, 16 V,+/- 10%, X7R, 0402; Manufacturer: Kemet; TaMin_C: -55°C; Polarized: N; Green_Lifecycle: Active; SizeAreaWB_mm2: 3; Green_REACh: Passed; U/M: EA; Value: 0.01uF; TaMax_C: 125°C; SizeZ_mm: 0.6; SizeX_mm: 1; SizeY_mm: 0.5; Cap_Case: 0402; Value2: 16V; Cap_F: 10nF; AEC Category: Q200
C34 = CMP-0064946-2: as C31 on sheet PROC177B_xWRL6432AoP_Chip
C35 = CMP-0085537-1: CAP, CERM, 1 µF, 16 V,+/- 10%, X7R, 0603; Manufacturer: Samsung Electro-Mechanics; SizeZ_mm: 1; SizeY_mm: 0.8; TaMin_C: -55°C; VDC_V: 16V; AEC Qualified: N; U/M: EA; AEC Category: Q200; SizeAreaWB_mm2: 4.68; TaMax_C: 125°C; SizeX_mm: 1.6; Value: 1uF; SizeArea_mm2: 1.28
R44 R49 = CMP-0001699-1: as R9 on sheet PROC177B_DC_Regulators
R45-R48 R51 = CMP-0120016-1: as R93 on sheet PROC177B_xWRL6432AoP_Chip
R50 = CMP-0120015-1: General Purpose Chip Resistor Thick Film 0402 47.5kOhm 1% Paper T/R; Manufacturer: YAGEO; AEC Qualified: No; Power_W: 63mW; SizeZ_mm: 0.4mm; TempCo: 100ppm/°C; VDC_V: 50V
U2 = CMP-0078466-1: ULTRA LOW POWER, 16M-BIT [x 1/x 2/x 4] CMOS MXSMIO (SERIAL MULTI I/O) FLASH MEMORY, SON-8; Manufacturer: Macronix International Co., LTD; SizeArea_mm2: 6; SizeAreaWB_mm2: 12; SizeY_mm: 2; SizeZ_mm: 0.6; SizeX_mm: 3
